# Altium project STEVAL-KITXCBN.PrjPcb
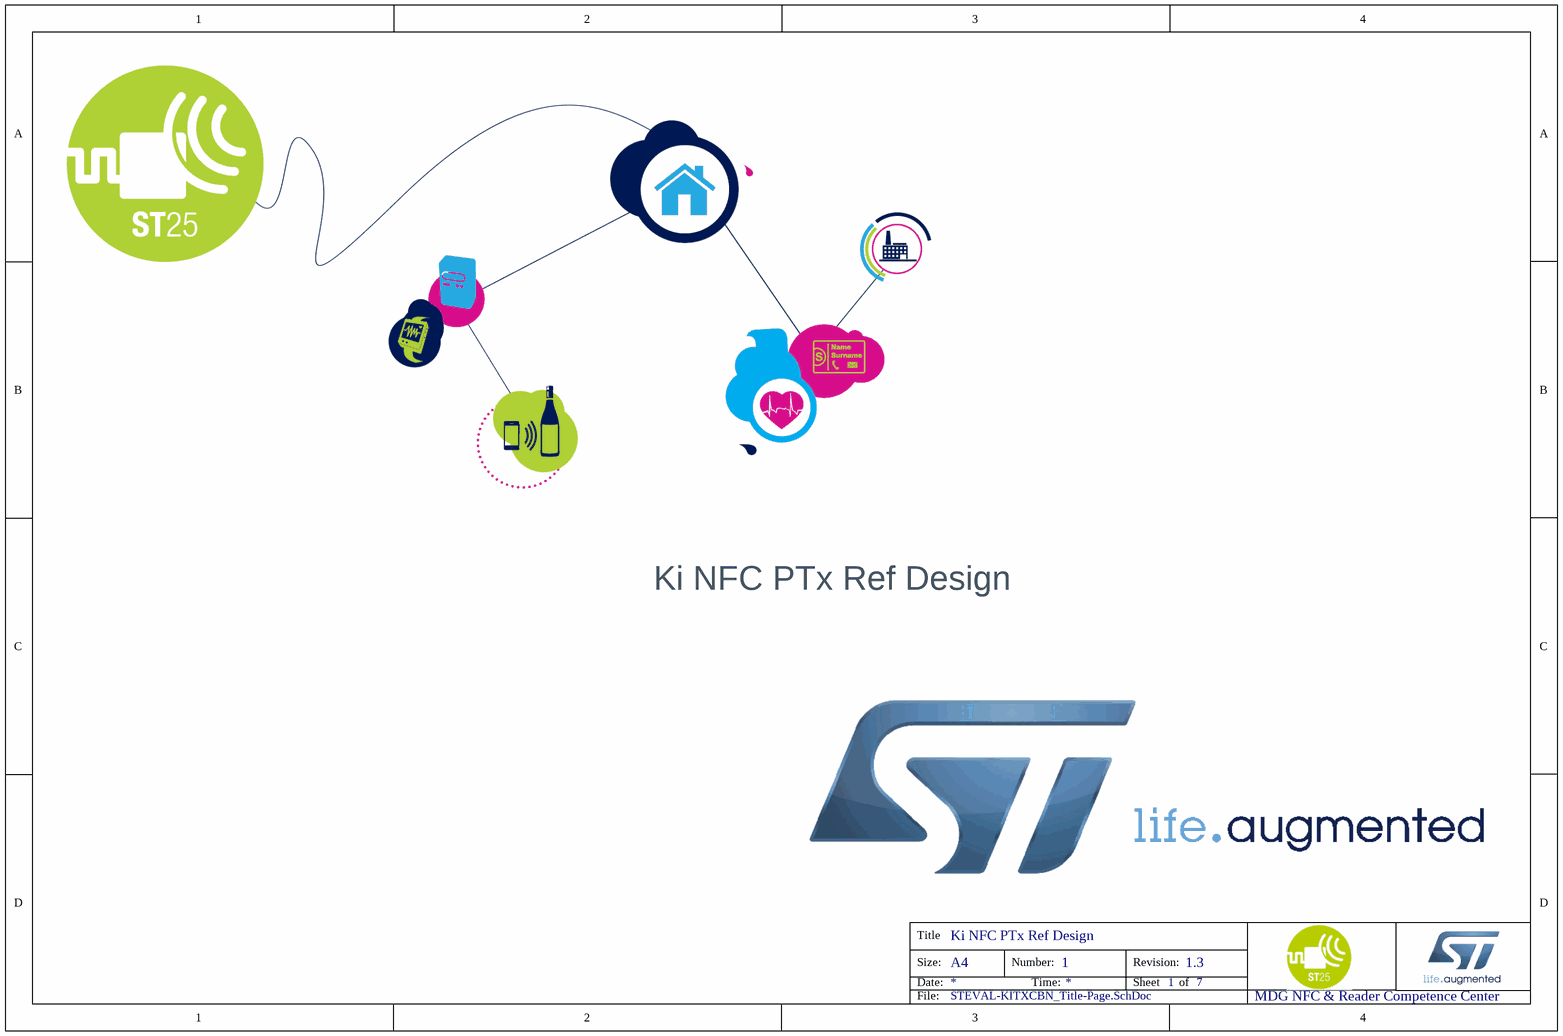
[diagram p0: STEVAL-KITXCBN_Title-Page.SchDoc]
BoardCat: Ki; BoardRef: ST25R3916-Ki; BoardRev: 1.3; Originator: rampetsm; ProjDate: 11.01.2022; ProjTitle: Ki NFC PTx Ref Design; SocProj: None; TotalNrSheets: 7
7 sheets, 229 parts. Net scope: hierarchical (ports join the sheet entries above them; power ports are global).
Board file: STEVAL-KITXCBN.PcbDoc
Sheets:
  STEVAL-KITXCBN_Title-Page.SchDoc
  STEVAL-KITXCBN_Main-Page.SchDoc
  STEVAL-KITXCBN_MCU-Connector.SchDoc
  STEVAL-KITXCBN_Microcontroller.SchDoc
  STEVAL-KITXCBN_NFC.SchDoc
  STEVAL-KITXCBN_Powerstage.SchDoc
  STEVAL-KITXCBN_Power-Supply.SchDoc

## Sheet STEVAL-KITXCBN_Title-Page.SchDoc
size A4; DocumentNumber: 1; SheetNumber: 1; SheetTotal: 7; PageSetup: Record=PageOptions¦CenterHorizontal=True¦CenterVertical=True¦PrintScale=1.00¦XCorrection=1.00¦YCorrection=1.00¦PrintKind=0¦BorderSize=5000000¦LeftOffset=0¦BottomOffset=0¦Orientation=2¦PaperLength=1000¦PaperWidth=1000¦Scale=100¦PaperSource=7¦PrintQuality=-3¦MediaType=1¦DitherType=10¦PrintScaleMode=1¦PaperKind=A4¦PaperIndex=9

## Sheet STEVAL-KITXCBN_Main-Page.SchDoc
size A4; DocumentNumber: 2; SheetNumber: 2; SheetTotal: 7; PageSetup: Record=PageOptions¦CenterHorizontal=True¦CenterVertical=True¦PrintScale=1.00¦XCorrection=1.00¦YCorrection=1.00¦PrintKind=0¦BorderSize=5000000¦LeftOffset=0¦BottomOffset=0¦Orientation=2¦PaperLength=1000¦PaperWidth=1000¦Scale=100¦PaperSource=7¦PrintQuality=-4¦MediaType=1¦DitherType=10¦PrintScaleMode=1¦PaperKind=A4
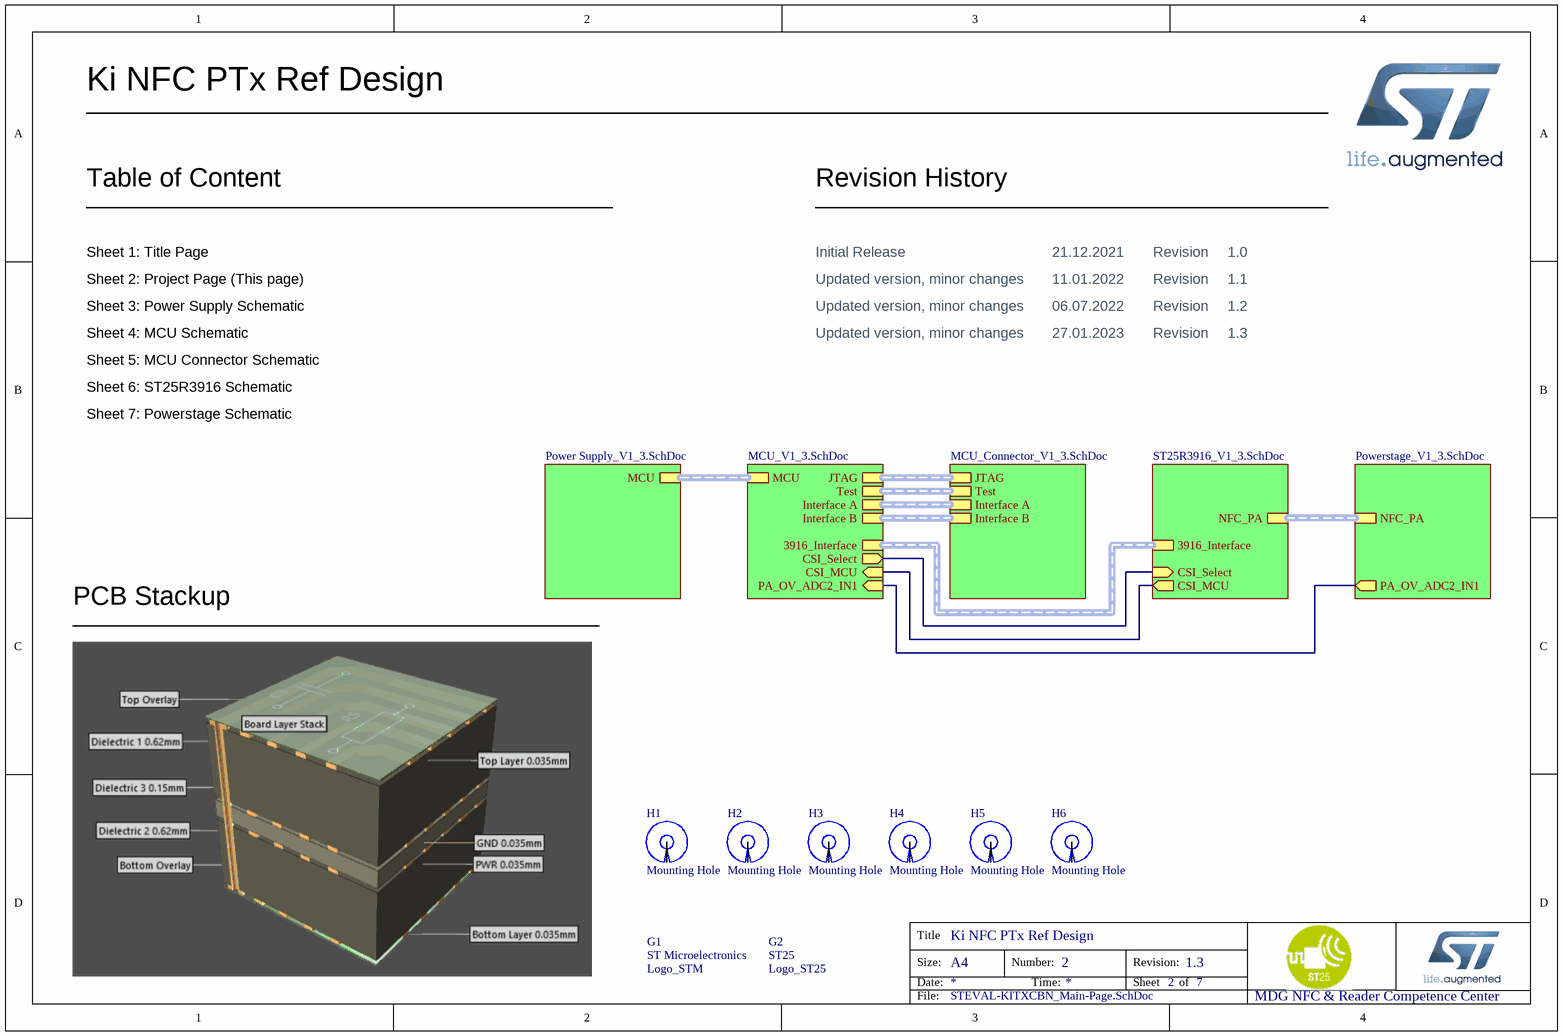
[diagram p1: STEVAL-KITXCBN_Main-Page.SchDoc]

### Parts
G1  Logo_STM  [Logo_STM]
G2  Logo_ST25  [Logo_ST25]
H1  Mounting Hole  [HOLE_M3]  (no BOM)
H2  Mounting Hole  [HOLE_M3]  (no BOM)
H3  Mounting Hole  [HOLE_M3]  (no BOM)
H4  Mounting Hole  [HOLE_M3]  (no BOM)
H5  Mounting Hole  [HOLE_M3]  (no BOM)
H6  Mounting Hole  [HOLE_M3]  (no BOM)

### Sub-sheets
Designator = Power Supply_V1_3.SchDoc (file not in this document): MCU (harness MCU)
Designator = MCU_V1_3.SchDoc (file not in this document): JTAG (harness JTAG), PA_OV_ADC2_IN1 (in), CSI_Select (out), CSI_MCU (in), MCU (harness MCU), 3916_Interface (harness 3916_Interface), Interface A (harness Interface A), Test (harness Test), Interface B (harness Interface B)
Designator = MCU_Connector_V1_3.SchDoc (file not in this document): JTAG (harness JTAG), Interface A (harness Interface A), Interface B (harness Interface B), Test (harness Test)
Designator = ST25R3916_V1_3.SchDoc (file not in this document): CSI_Select (in), CSI_MCU (out), 3916_Interface (harness 3916_Interface), NFC_PA (harness *)
Designator = Powerstage_V1_3.SchDoc (file not in this document): PA_OV_ADC2_IN1 (out), NFC_PA (harness *)

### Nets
(unnamed): sheet Designator/PA_OV_ADC2_IN1, sheet Designator/PA_OV_ADC2_IN1
(unnamed): sheet Designator/CSI_Select, sheet Designator/CSI_Select  [a separate net that carries the same name]
(unnamed): sheet Designator/CSI_MCU, sheet Designator/CSI_MCU  [a separate net that carries the same name]

Not connected (* = marked no-connect by the designer): H1 1; H2 1; H3 1; H4 1; H5 1; H6 1

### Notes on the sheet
- Table of Content
- Revision History
- Sheet 1: Title Page
- Sheet 2: Project Page (This page)
- Sheet 3: Power Supply Schematic
- Initial Release
- Updated version, minor changes
- 21.12.2021
- 06.07.2022
- 11.01.2022
- Revision
- 1.0
- 1.2
- 1.1
- Sheet 4: MCU Schematic
- Sheet 5: MCU Connector Schematic
- 27.01.2023
- 1.3
- Sheet 6: ST25R3916 Schematic
- Sheet 7: Powerstage Schematic
- PCB Stackup

## Sheet STEVAL-KITXCBN_MCU-Connector.SchDoc
size A4; DocumentNumber: 5; SheetNumber: 5; SheetTotal: 7
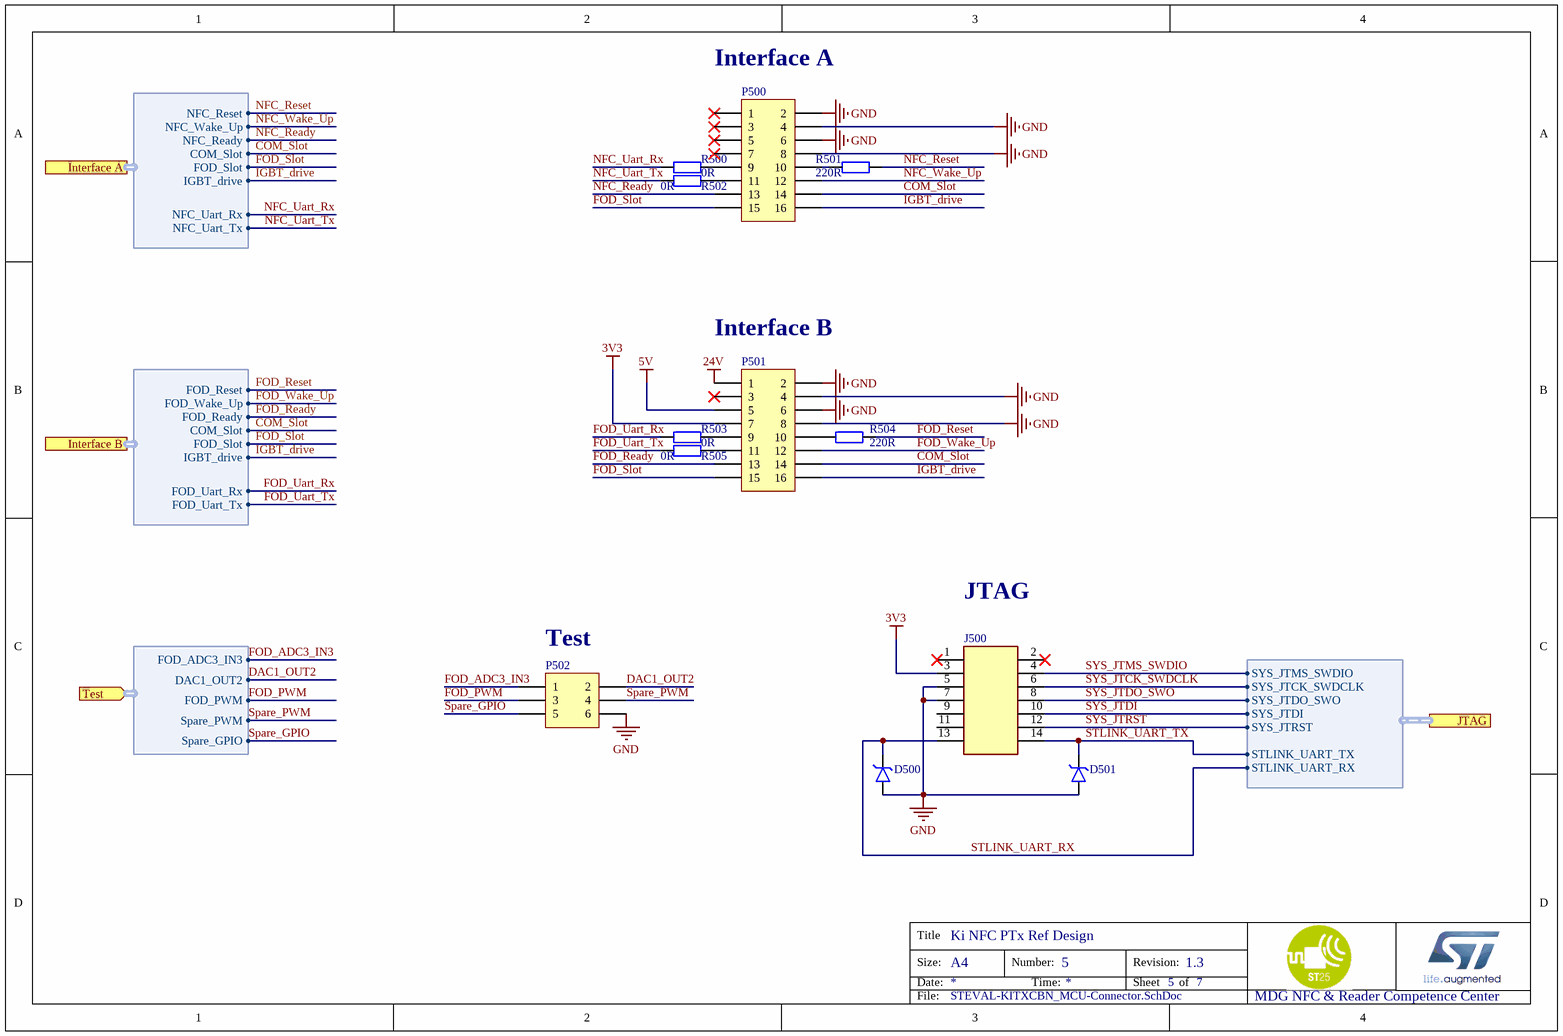
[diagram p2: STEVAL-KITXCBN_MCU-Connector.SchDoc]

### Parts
D500  ESDALC6V1-1U2  [ST-ST0201]  (value not drawn)
D501  ESDALC6V1-1U2  [ST-ST0201]  (value not drawn)
J500  FTSH-107-01-L-DV-K-A  [SAMTEC-FTSH-107-01-X-DV-K-A-WITH-FFSD]  (value not drawn)
P500  Header 8X2_3D_female  [HDR2X8_3D_female]  (value not drawn)
P501  Header 8X2_3D_male  [HDR2X8_3D_male]  (value not drawn)
P502  Header 3X2_3D_male  [HDR2X3_3D_male]  (value not drawn)
R500  0R  [RES_SMD_0805]
R501  220R  [RES_SMD_0805]
R502  0R  [RES_SMD_0805]
R503  0R  [RES_SMD_0805]
R504  220R  [RES_SMD_0805]
R505  0R  [RES_SMD_0805]

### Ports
Interface A (harness Interface A), Interface B (harness Interface B), JTAG (harness JTAG), Test (in, harness Test)

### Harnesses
Interface B: FOD_Slot, IGBT_drive, FOD_Wake_Up, FOD_Reset, COM_Slot, FOD_Uart_Rx, FOD_Uart_Tx, FOD_Ready
Interface A: FOD_Slot, IGBT_drive, NFC_Wake_Up, NFC_Reset, COM_Slot, NFC_Uart_Rx, NFC_Uart_Tx, NFC_Ready
JTAG: SYS_JTMS_SWDIO, SYS_JTCK_SWDCLK, SYS_JTDO_SWO, SYS_JTDI, SYS_JTRST, STLINK_UART_TX, STLINK_UART_RX
Test: FOD_ADC3_IN3, DAC1_OUT2, FOD_PWM, Spare_PWM, Spare_GPIO

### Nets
3V3: J500.3 P501.7
5V: P501.5
24V: P501.1
GND: D500.A D501.A J500.5 J500.7 P500.2 P500.4 P500.6 P500.8 P501.2 P501.4 P501.6 P501.8 P502.6
COM_Slot: P500.14 P501.14 ; port Interface B.COM_Slot, port Interface A.COM_Slot
DAC1_OUT2: P502.2 ; port Test.DAC1_OUT2
FOD_ADC3_IN3: P502.1 ; port Test.FOD_ADC3_IN3
FOD_PWM: P502.3 ; port Test.FOD_PWM
FOD_Ready: P501.13 ; port Interface B.FOD_Ready
FOD_Reset: R504.2 ; port Interface B.FOD_Reset
FOD_Slot: P500.15 P501.15 ; port Interface B.FOD_Slot, port Interface A.FOD_Slot
FOD_Uart_Rx: R503.1 ; port Interface B.FOD_Uart_Rx
FOD_Uart_Tx: R505.1 ; port Interface B.FOD_Uart_Tx
FOD_Wake_Up: P501.12 ; port Interface B.FOD_Wake_Up
IGBT_drive: P500.16 P501.16 ; port Interface B.IGBT_drive, port Interface A.IGBT_drive
NFC_Ready: P500.13 ; port Interface A.NFC_Ready
NFC_Reset: R501.2 ; port Interface A.NFC_Reset
NFC_Uart_Rx: R500.1 ; port Interface A.NFC_Uart_Rx
NFC_Uart_Tx: R502.1 ; port Interface A.NFC_Uart_Tx
NFC_Wake_Up: P500.12 ; port Interface A.NFC_Wake_Up
Spare_GPIO: P502.5 ; port Test.Spare_GPIO
Spare_PWM: P502.4 ; port Test.Spare_PWM
STLINK_UART_RX: D500.K J500.13 ; port JTAG.STLINK_UART_RX
STLINK_UART_TX: D501.K J500.14 ; port JTAG.STLINK_UART_TX
SYS_JTCK_SWDCLK: J500.6 ; port JTAG.SYS_JTCK_SWDCLK
SYS_JTDI: J500.10 ; port JTAG.SYS_JTDI
SYS_JTDO_SWO: J500.8 ; port JTAG.SYS_JTDO_SWO
SYS_JTMS_SWDIO: J500.4 ; port JTAG.SYS_JTMS_SWDIO
SYS_JTRST: J500.12 ; port JTAG.SYS_JTRST
NetP500_9: P500.9 R500.2
NetP500_10: P500.10 R501.1
NetP500_11: P500.11 R502.2
NetP501_9: P501.9 R503.2
NetP501_10: P501.10 R504.1
NetP501_11: P501.11 R505.2

Not connected (* = marked no-connect by the designer): J500 1* 2* 9 11; P500 1* 3* 5* 7*; P501 3*

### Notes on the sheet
- (near P500) Interface A
- (near P501) Interface B
- (near P502) Test
- JTAG

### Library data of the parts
D500 D501 = ESDALC6V1-1U2: ESD PROTECT TRANSIL ESDALC6V1-1U2; Manufacturer: ST MICRO; VERIFIE: YES
J500 = FTSH-107-01-L-DV-K-A: CONNECTOR FTSH-107-01-L-DV-K-A; Manufacturer: SAMTEC; VERIFIE: YES
P500 = Header 8X2_3D_female: Board Connector, 16 Contact(s), 2 Row(s), Female, Straight, 0.1 inch Pitch, Solder Terminal, Black Insulator, Socket; Manufacturer: Würth Electronics; Manufacturer Part Number: 61301621121; Option: General Purpose; Contact Pattern: RECTANGULAR; Contact Style: SQ PIN-SKT; Filter Feature: No; Number Of Connectors: 1; Number Of PCB Rows: 2; Number of Contacts: 16; Contact Resistance: 10mR; Mating Information: MULTIPLE MATING PARTS AVAILABLE; Additional Feature: TIGER BUY CONTACT; Body Breadth: 0.195inch; PCB Contact Row Spacing: 2.54mm; Plating Thickness: 20uin; Body Depth: 0.335inch; Reference Standard: UL; Reliability: COMMERCIAL
P501 = Header 8X2_3D_male: Board Connector, 16 Contact(s), 2 Row(s), Male, Straight, 0.1 inch Pitch, Solder Terminal; Manufacturer: Würth Electronics; Manufacturer Part Number: 61301621121; Manufacturer Series: HTSW; Option: General Purpose; Filter Feature: No; Mating Information: MULTIPLE MATING PARTS AVAILABLE; Number of Rows Loaded: 2; Number of Contacts: 16; Additional Feature: E.L.P.
P502 = Header 3X2_3D_male: Board Connector, 6 Contact(s), 2 Row(s), Male, Straight, 0.1 inch Pitch, Solder Terminal, Black Insulator; Manufacturer: Samtec; Manufacturer Part Number: TSW-103-07-F-D; Option: General Purpose; Additional Feature: E.L.P.; Filter Feature: No; Number of Rows Loaded: 2; Number of Contacts: 6; Mating Information: MULTIPLE MATING PARTS AVAILABLE; Contact Pattern: RECTANGULAR; Contact Style: SQ PIN-SKT; Number Of Connectors: 1; PCB Contact Row Spacing: 5.08mm; Reference Standard: UL; Reliability: COMMERCIAL
R500 R502 R503 R505 = RESISTOR: Metal Glaze/thick Film, 0.0625W, 0ohm, Surface Mount, 0402; Manufacturer: Yageo; Manufacturer Part Number: RC0402JR-070RL; TSL: Yes; Tolerance: 1%; Rated Power Dissipation (P): 62.5mW; Rated Temperature: 70°C; Package Height: 0.35mm; Package Length: 1mm; Package Width: 0.5mm
R501 R504 = RESISTOR: TSL: Yes; Tolerance: 1%

## Sheet STEVAL-KITXCBN_Microcontroller.SchDoc
size A4; DocumentNumber: 4; SheetNumber: 4; SheetTotal: 7
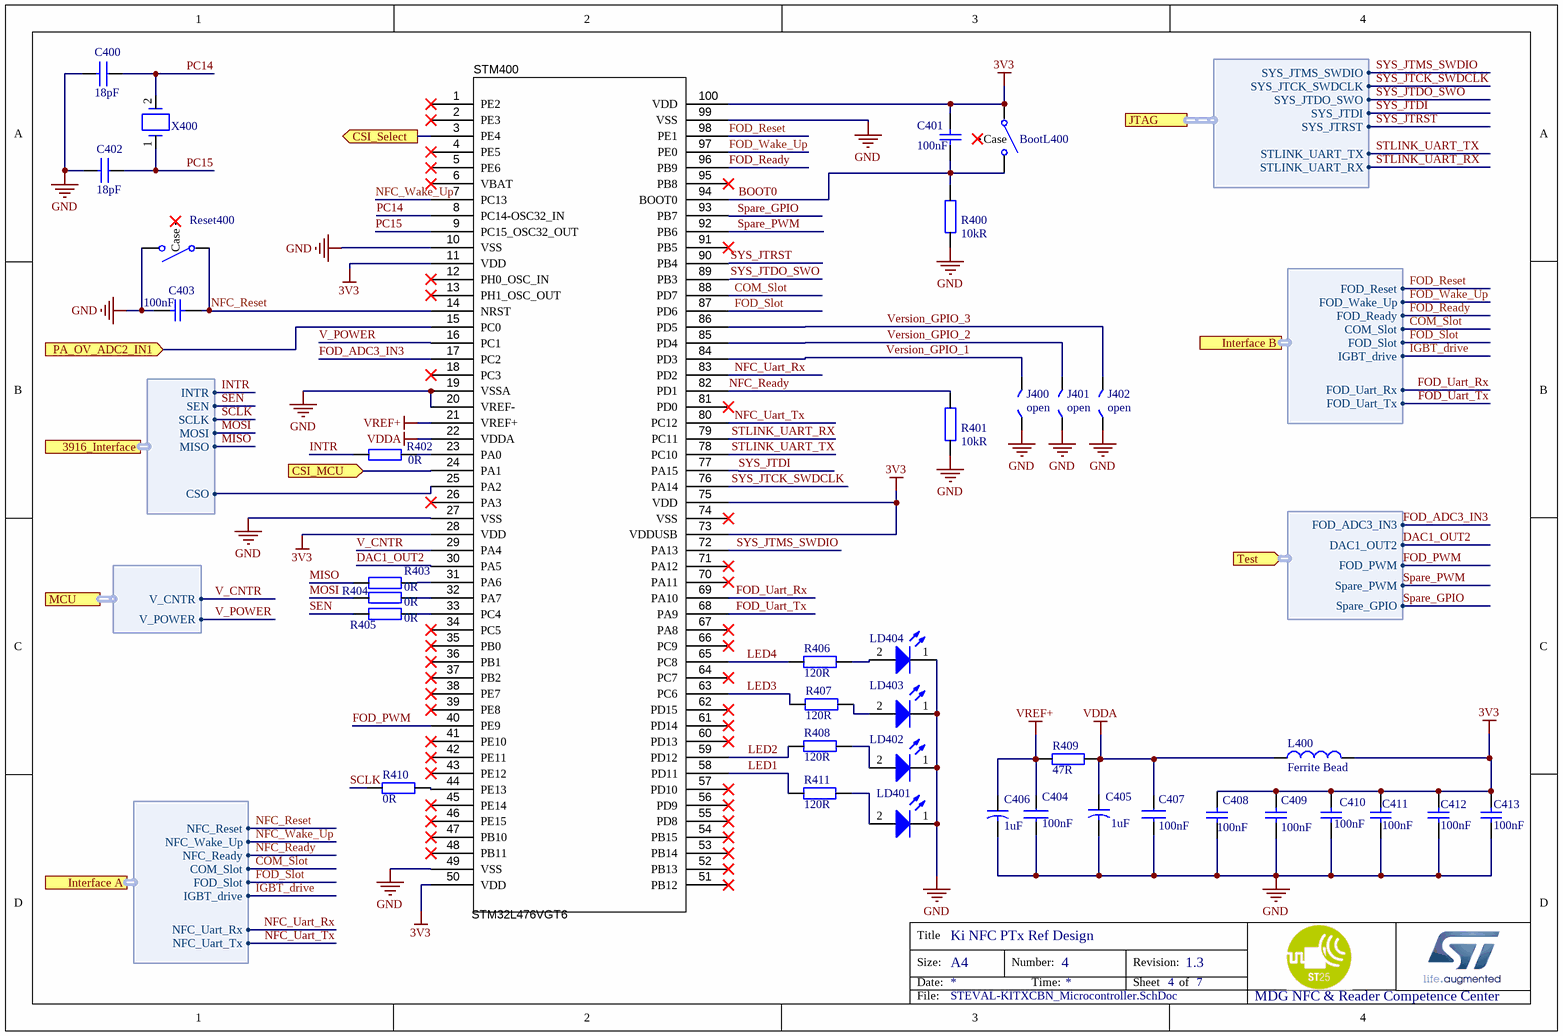
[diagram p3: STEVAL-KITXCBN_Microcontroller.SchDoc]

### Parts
BootL400  PushButton  [SW_SPST_KMR211G]  (value not drawn)
C400  18pF  [C0402]
C401  100nF  [C0402-ss]
C402  18pF  [C0402]
C403  100nF  [C0402-ss]
C404  100nF  [C0402]
C405  1uF  [CP_SMD_A]
C406  1uF  [CP_SMD_A]
C407  100nF  [C0402]
C408  100nF  [C0402-ss]
C409  100nF  [C0402-ss]
C410  100nF  [C0402-ss]
C411  100nF  [C0402-ss]
C412  100nF  [C0402-ss]
C413  100nF  [C0402-ss]
J400  open  [JP2_SMD_open]  (no BOM)
J401  open  [JP2_SMD_open]  (no BOM)
J402  open  [JP2_SMD_open]  (no BOM)
L400  Ferrite Bead  [0603-CAP]
LD401  White LED  [0603D]  (value not drawn)
LD402  White LED  [0603D]  (value not drawn)
LD403  White LED  [0603D]  (value not drawn)
LD404  White LED  [0603D]  (value not drawn)
R400  10kR  [R0402]
R401  10kR  [R0402]
R402  0R  [R0402]
R403  0R  [R0402]
R404  0R  [R0402]
R405  0R  [R0402]
R406  120R  [R0402]
R407  120R  [R0402]
R408  120R  [R0402]
R409  47R  [R0402]
R410  0R  [R0402]
R411  120R  [R0402]
Reset400  PushButton  [SW_SPST_KMR211G]  (value not drawn)
STM400  STM32L476VGT6  [STM32L476VGT6 LQFP100]
X400  32_768kHz  [32_768kHz_Crystal]  (value not drawn)

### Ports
3916_Interface (harness 3916_Interface), CSI_MCU (in), CSI_Select (out), Interface A (harness Interface A), Interface B (harness Interface B), JTAG (harness JTAG), MCU (harness MCU), PA_OV_ADC2_IN1 (in), Test (in, harness Test)

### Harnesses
MCU: V_POWER, V_CNTR
3916_Interface: SEN, INTR, MISO, MOSI, SCLK, CSO
JTAG: SYS_JTMS_SWDIO, SYS_JTCK_SWDCLK, SYS_JTDO_SWO, SYS_JTDI, SYS_JTRST, STLINK_UART_TX, STLINK_UART_RX
Test: FOD_ADC3_IN3, DAC1_OUT2, FOD_PWM, Spare_PWM, Spare_GPIO
Interface A: FOD_Slot, IGBT_drive, NFC_Wake_Up, NFC_Reset, COM_Slot, NFC_Uart_Rx, NFC_Uart_Tx, NFC_Ready
Interface B: FOD_Slot, IGBT_drive, FOD_Wake_Up, FOD_Reset, COM_Slot, FOD_Uart_Rx, FOD_Uart_Tx, FOD_Ready

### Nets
3V3: BootL400.2 C401.1 C408.2 C409.2 C410.2 C411.2 C412.2 C413.2 L400.2 STM400.11(VDD) STM400.28(VDD) STM400.50(VDD) STM400.73(VDDUSB) STM400.75(VDD) STM400.100(VDD)
GND: C400.2 C402.2 C403.1 C404.2 C405.2 C406.2 C407.2 C408.1 C409.1 C410.1 C411.1 C412.1 C413.1 J400.1 J401.1 J402.1 LD401.1(K) LD402.1(K) LD403.1(K) LD404.1(K) R400.1 R401.1 Reset400.1 STM400.10(VSS) STM400.19(VSSA) STM400.20(VREF-) STM400.27(VSS) STM400.49(VSS) STM400.99(VSS)
VDDA: C405.1 C407.1 L400.1 R409.1 STM400.22(VDDA)
VREF+: C404.1 C406.1 R409.2 STM400.21(VREF+)
BOOT0: BootL400.1 C401.2 R400.2 STM400.94(BOOT0)
COM_Slot: STM400.88(PD7) ; port Interface A.COM_Slot, port Interface B.COM_Slot
DAC1_OUT2: STM400.30(PA5) ; port Test.DAC1_OUT2
FOD_ADC3_IN3: STM400.17(PC2) ; port Test.FOD_ADC3_IN3
FOD_PWM: STM400.40(PE9) ; port Test.FOD_PWM
FOD_Ready: STM400.96(PB9) ; port Interface B.FOD_Ready
FOD_Reset: STM400.98(PE1) ; port Interface B.FOD_Reset
FOD_Slot: STM400.87(PD6) ; port Interface A.FOD_Slot, port Interface B.FOD_Slot
FOD_Uart_Rx: STM400.69(PA10) ; port Interface B.FOD_Uart_Rx
FOD_Uart_Tx: STM400.68(PA9) ; port Interface B.FOD_Uart_Tx
FOD_Wake_Up: STM400.97(PE0) ; port Interface B.FOD_Wake_Up
IGBT_drive: port Interface A.IGBT_drive, port Interface B.IGBT_drive
INTR: R402.1 ; port 3916_Interface.INTR
LED1: R411.1 STM400.58(PD11)
LED2: R408.1 STM400.59(PD12)
LED3: R407.1 STM400.63(PC6)
LED4: R406.1 STM400.65(PC8)
MISO: R403.1 ; port 3916_Interface.MISO
MOSI: R404.1 ; port 3916_Interface.MOSI
NFC_Ready: R401.2 STM400.82(PD1) ; port Interface A.NFC_Ready
NFC_Reset: C403.2 Reset400.2 STM400.14(NRST) ; port Interface A.NFC_Reset
NFC_Uart_Rx: STM400.83(PD2) ; port Interface A.NFC_Uart_Rx
NFC_Uart_Tx: STM400.80(PC12) ; port Interface A.NFC_Uart_Tx
NFC_Wake_Up: STM400.7(PC13) ; port Interface A.NFC_Wake_Up
PC14: C400.1 STM400.8(PC14-OSC32_IN) X400.2
PC15: C402.1 STM400.9(PC15_OSC32_OUT) X400.1
SCLK: R410.1 ; port 3916_Interface.SCLK
SEN: R405.1 ; port 3916_Interface.SEN
Spare_GPIO: STM400.93(PB7) ; port Test.Spare_GPIO
Spare_PWM: STM400.92(PB6) ; port Test.Spare_PWM
STLINK_UART_RX: STM400.79(PC11) ; port JTAG.STLINK_UART_RX
STLINK_UART_TX: STM400.78(PC10) ; port JTAG.STLINK_UART_TX
SYS_JTCK_SWDCLK: STM400.76(PA14) ; port JTAG.SYS_JTCK_SWDCLK
SYS_JTDI: STM400.77(PA15) ; port JTAG.SYS_JTDI
SYS_JTDO_SWO: STM400.89(PB3) ; port JTAG.SYS_JTDO_SWO
SYS_JTMS_SWDIO: STM400.72(PA13) ; port JTAG.SYS_JTMS_SWDIO
SYS_JTRST: STM400.90(PB4) ; port JTAG.SYS_JTRST
V_CNTR: STM400.29(PA4) ; port MCU.V_CNTR
V_POWER: STM400.16(PC1) ; port MCU.V_POWER
Version_GPIO_1: J400.2 STM400.84(PD3)
Version_GPIO_2: J401.2 STM400.85(PD4)
Version_GPIO_3: J402.2 STM400.86(PD5)
NetLD401_2: LD401.2(A) R411.2
NetLD402_2: LD402.2(A) R408.2
NetLD403_2: LD403.2(A) R407.2
NetLD404_2: LD404.2(A) R406.2
NetR402_2: R402.2 STM400.23(PA0)
NetR403_2: R403.2 STM400.31(PA6)
NetR404_2: R404.2 STM400.32(PA7)
NetR405_2: R405.2 STM400.33(PC4)
NetR410_2: R410.2 STM400.44(PE13)
NetSTM400_3: STM400.3(PE4) ; port CSI_Select
NetSTM400_15: STM400.15(PC0) ; port PA_OV_ADC2_IN1
NetSTM400_24: STM400.24(PA1) ; port CSI_MCU
NetSTM400_25: STM400.25(PA2) ; port 3916_Interface.CSO

Not connected (* = marked no-connect by the designer): BootL400 0(Case)*; Reset400 0(Case)*; STM400 1(PE2)* 2(PE3)* 4(PE5)* 5(PE6)* 6(VBAT)* 12(PH0_OSC_IN)* 13(PH1_OSC_OUT)* 18(PC3)* 26(PA3)* 34(PC5)* 35(PB0)* 36(PB1)* 37(PB2)* 38(PE7)* 39(PE8)* 41(PE10)* 42(PE11)* 43(PE12)* 45(PE14)* 46(PE15)* 47(PB10)* 48(PB11)* 51(PB12)* 52(PB13)* 53(PB14)* 54(PB15)* 55(PD8)* 56(PD9)* 57(PD10)* 60(PD13)* 61(PD14)* 62(PD15)* 64(PC7)* 66(PC9)* 67(PA8)* 70(PA11)* 71(PA12)* 74(VSS)* 81(PD0)* 91(PB5)* 95(PB8)*

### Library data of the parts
BootL400 Reset400 = SW_SPST2_GND: SWITCH TACTILE SPST-NO 0.05A 32V; Manufacturer: ITT C&K; Manufacturer Part Number: KMR211GLFS; Mechanical Life: 200000Cycles; Power Rating: 1W; Contact Current Rating: 50mA; Operating Force: 1.2N; Throw Configuration: SPST; Illumination Type: Non-Illuminated,Illuminated; Switch Travel: 0.2mm; Switch Function: Off-Mom; Actuator Type: Standard; Actuator Length: 0.5mm
C400 C402 = C_0402: CAPACITOR CERAMIC 18PF 50V, C0G, 5%, 040; Manufacturer: Kyocera AVX; Manufacturer Part Number: 04025A180JAT2A; Temperature Coefficient: 0ppm/°C; Insulation Resistance: 100GR
C401 C403 = C_0603: Capacitor 100 nF 10 VDC 0402 ¦ KEMET C0402C104K8PACTU (Capacitor 100 nF 10 VDC 0402 Ceramic Capacitors).; Tolerance: 10%; Voltage Rating: 10V; Dielectric: X5R; Dissipation Factor: 5%
C404 C407 = C_0402: Manufacturer: Murata; Manufacturer Part Number: GRM155R61H104KE19D; Capacitance: 100; Tolerance: 10; Voltage Rating: 50; Type (Capacitors): X5R
C405 C406 = C_POL_A: Manufacturer: Kyocera / AVX; Manufacturer Part Number: TAJA105K016RNJ; Capacitance: 1; Tolerance: 10; ESR: 11; Voltage Rating: 16
C408-C413 = C_0603: Manufacturer: MURATA; Manufacturer Part Number: GRM155R61H104KE19D; Produktpalette: Baureihe GRM; Kapazität: 0.1; Kapazitätstoleranz: ± 10%; Dielektrikum: X5; Nennspannung: 50; Keramikkondensatorgehäuse: 0402 [Metrisch 1005]; Betriebstemperatur, min.: -55; Betriebstemperatur, max.: 85; Verpackung: Gurtabschnitt; SVHC: No SVHC (15-Jun-2015); Kondensatoranschlüsse: SMD<!--FANDB--><div class="features-and-benefits-container"><div class="features-and-benefits-description"><span class="features-benefits-value">The Murata GRM series capacitors are Multilayer Ceramic Chip Capacitors (MLCC) used for general purpose applications. These MLCC capacitors are classified into temperature compensating and high dielectric constant types depending on the change in electrostatic capacitance due to change in temperature. The temperature compensating capacitors feature a small rate of change in electrostatic capacitance as the temperature changes and are used for applications such as filters and high frequency circuit matching. The high dielectric constant capacitors use materials with a high dielectric constant and feature a large electrostatic capacitance. Typical applications are power supply decoupling and smoothing circuits.</span></div><div class="features-and-benefits-list"><ul class="features-and-benefits-list-list"><li class="features-and-benefits-list-item">Large capacity and small size in a multilayer structure</li><li class="features-and-benefits-list-item">Capacitance value ranging from 0.1pF to 220?F</li><li class="features-and-benefits-list-item">Tin plated external electrodes, excellent solderability</li><li class="features-and-benefits-list-item">Provides good high frequency characteristics</li><li class="features-and-benefits-list-item">Excellent pulse response</li><li class="features-and-benefits-list-item">High reliability</li><li class="features-and-benefits-list-item">Capacitor size varies from 0.4×0.2mm to 5.7×5.0mm</li><li class="features-and-benefits-list-item">Rated voltage of 2.5VDC to 3.15
J400-J402 = solder_jumper_open
L400 = BLM18AG601SN1D: Ferrite Chip, 1 Function(s), 0.5A, 2 Pin(s); Manufacturer: MURATA; VERIFIE: YES; DC Resistance-Max: 380mR; Max Frequency: 100MHz; Number of Functions: 1; Output Impedance: 600R; Current Rating: 500mA
LD401-LD404 = LED2: LED Uni-Color White 7000K 2-Pin Chip 0603(1608Metric) T/R / LED COOL WHITE 0603 SMD; Manufacturer: Vishay Semiconductors; Manufacturer Part Number: VLMW1300-GS08; Luminous Intensity: 180mcd; Forward Voltage: 3.15V; Viewing Angle: 130°; Lens Style: Square,Rectangular,Clear; Forward Current: 5mA; Power Rating: 70mW; Number of LEDs: 1
R400 R401 = R_0402: Fixed Resistor, Metal Glaze/thick Film, 0.1W, 10000ohm, 50V, 1% +/-Tol, 200ppm/Cel, Surface Mount, 0402; Manufacturer: Panasonic; Manufacturer Part Number: ERJ-U02F1002X; Rated Power Dissipation (P): 100mW; Rated Temperature: 70°C; Temperature Coefficient: 200ppm/°C; Package Height: 0.35mm; Package Length: 1mm; Package Width: 0.5mm; Reference Standard: AEC-Q200
R402-R405 R410 = R_0402: Metal Glaze/thick Film, 0.0625W, 0ohm, Surface Mount, 0402; Manufacturer: Yageo; Manufacturer Part Number: RC0402JR-070RL; Rated Power Dissipation (P): 62.5mW; Rated Temperature: 70°C; Package Height: 0.35mm; Package Length: 1mm; Package Width: 0.5mm
R406-R408 R411 = R_0402: VISHAY - CRCW0402120RFKED - RES, THICK FILM, 120R, 1%, 0.063W, 0402, REEL; Temperature Coefficient: 100ppm/°C; Power Rating: 63mW; Voltage Rating: 50V
R409 = R_0402: VISHAY - CRCW040247R0FKED - SMD Chip Resistor, 0402 [1005 Metric], 47 ohm, CRCW e3 Series, 50 V, Thick Film, 63 mW; Tolerance: 1%; Temperature Coefficient: 100ppm/°C; Voltage Rating: 50V; Power Rating: 63mW
STM400 = STM32L476VGT6: RISC Microcontroller, 32-Bit, FLASH, CORTEX-M4 CPU, 80MHz, CMOS, PQFP100; Manufacturer: STMicroelectronics
X400 = 32_768kHz_Crystal: FOX ELECTRONICS         FX135A-327            CRYSTAL, 32.768KHZ, 9PF, 3.2 X 1.5MM; Frequency Tolerance: 20ppm; Load Capacitance: 12.5pF; Series Resistance: 70kR; Frequency Stability: -0.045ppm; Operating Frequency: 32.768 MHz

## Sheet STEVAL-KITXCBN_NFC.SchDoc
size A4; DocumentNumber: 6; SheetNumber: 5; SheetTotal: 7
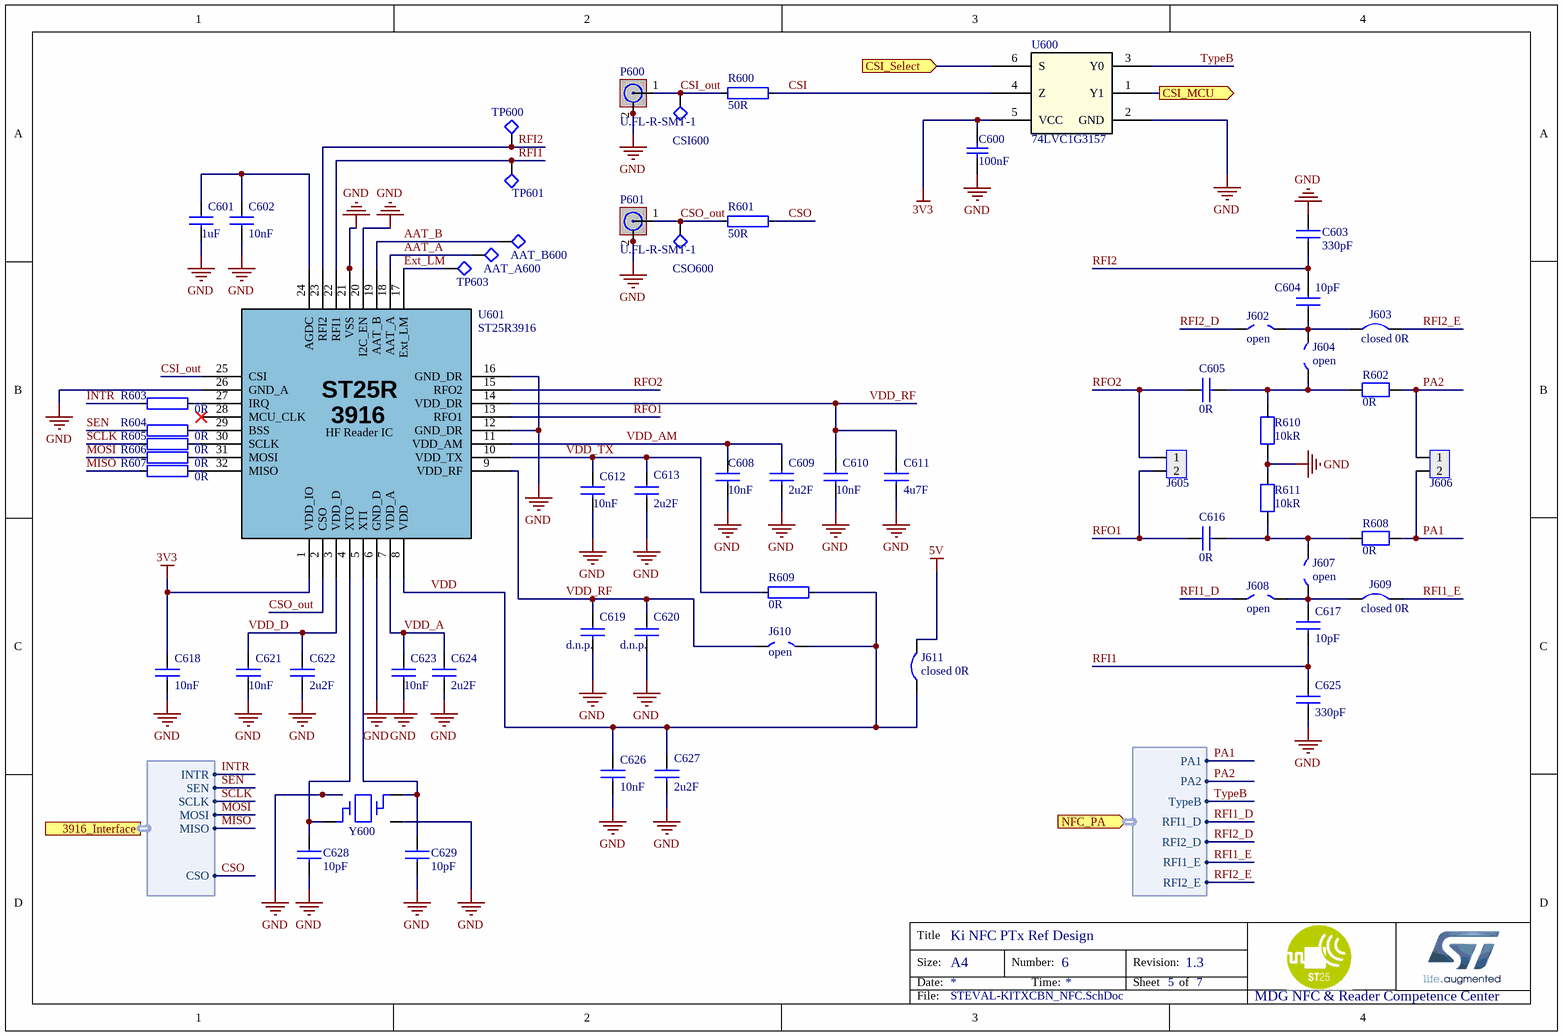
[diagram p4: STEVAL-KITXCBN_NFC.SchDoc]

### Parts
AAT_A600  *  [TP_0.5]  (value not drawn)  (no BOM)
AAT_B600  *  [TP_0.5]  (value not drawn)  (no BOM)
C600  100nF  [C0402-ss]
C601  1uF  [C0402]
C602  10nF  [C0402]
C603  330pF  [C0603]
C604  10pF  [C0603]
C605  0R  [C0603]
C608  10nF  [C0402]
C609  2u2F  [C0402]
C610  10nF  [C0402]
C611  4u7F  [C0402]
C612  10nF  [C0402]
C613  2u2F  [C0402]
C616  0R  [C0603]
C617  10pF  [C0603]
C618  10nF  [C0402]
C619  d.n.p.  [C0402]
C620  d.n.p.  [C0402]
C621  10nF  [C0402]
C622  2u2F  [C0402]
C623  10nF  [C0402]
C624  2u2F  [C0402]
C625  330pF  [C0603]
C626  10nF  [C0402]
C627  2u2F  [C0402]
C628  10pF  [C0402]
C629  10pF  [C0402]
CSI600  *  [TP_0.5]  (value not drawn)  (no BOM)
CSO600  *  [TP_0.5]  (value not drawn)  (no BOM)
J602  open  [JP2_SMD_open_0402]  (net tie, no BOM)
J603  closed 0R  [JP2_SMD_closed]  (net tie)
J604  open  [JP2_SMD_open_0402]  (net tie, no BOM)
J605  d.n.p.  [HDR1X2_slim]  (value not drawn)  (no BOM)
J606  d.n.p.  [HDR1X2_slim]  (value not drawn)  (no BOM)
J607  open  [JP2_SMD_open_0402]  (net tie, no BOM)
J608  open  [JP2_SMD_open_0402]  (net tie, no BOM)
J609  closed 0R  [JP2_SMD_closed]  (net tie)
J610  open  [JP2_SMD_open_0402]  (net tie, no BOM)
J611  closed 0R  [JP2_SMD_closed]  (net tie)
P600  U.FL-R-SMT-1  [U FL Socket - HRS - Surface Mount]
P601  U.FL-R-SMT-1  [U FL Socket - HRS - Surface Mount]
R600  50R  [R0402]
R601  50R  [R0402]
R602  0R  [R0603]
R603  0R  [R0402]
R604  0R  [R0402]
R605  0R  [R0402]
R606  0R  [R0402]
R607  0R  [R0402]
R608  0R  [R0603]
R609  0R  [R0402]
R610  10kR  [R0805]
R611  10kR  [R0805]
TP600  *  [TP_0.5]  (value not drawn)  (no BOM)
TP601  *  [TP_0.5]  (value not drawn)  (no BOM)
TP603  *  [TP_0.5]  (value not drawn)  (no BOM)
U600  74LVC1G3157  [XSON6_SOT1202]
U601  ST25R3916  [ST25R3916-QFN32_5X5_0.5]
Y600  NDK 27,12MHz Crystal  [XRCGB_F_MN]  (value not drawn)

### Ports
3916_Interface (harness 3916_Interface), CSI_MCU (out), CSI_Select (in), NFC_PA (in, harness *)

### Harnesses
3916_Interface: SEN, INTR, MISO, MOSI, SCLK, CSO
*: PA1, PA2, TypeB, RFI1_D, RFI2_D, RFI1_E, RFI2_E

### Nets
3V3: C600.2 C618.1 U600.5(VCC) U601.1(VDD_IO)
5V: J611.2
GND: C600.1 C601.2 C602.2 C603.1 C608.2 C609.2 C610.2 C611.2 C612.2 C613.2 C618.2 C619.2 C620.2 C621.2 C622.2 C623.2 C624.2 C625.2 C626.2 C627.2 C628.2 C629.2 P600.2 P600.3 P601.2 P601.3 R610.2 R611.1 U600.2(GND) U601.6(GND_D) U601.12(GND_DR) U601.16(GND_DR) U601.20(I2C_EN) U601.21(VSS) U601.26(GND_A) U601.33(VSS) Y600.2 Y600.4
AAT_A: AAT_A600.1 U601.18(AAT_A)
AAT_B: AAT_B600.1 U601.19(AAT_B)
CSI: R600.1 U600.4(Z)
CSI_out: CSI600.1 P600.1 R600.2 U601.25(CSI)
CSO: R601.1 ; port 3916_Interface.CSO
CSO_out: CSO600.1 P601.1 R601.2 U601.2(CSO)
Ext_LM: TP603.1 U601.17(Ext_LM)
INTR: R603.2 ; port 3916_Interface.INTR
MISO: R607.2 ; port 3916_Interface.MISO
MOSI: R606.2 ; port 3916_Interface.MOSI
PA1: J606.2 R608.2 ; port NFC_PA.PA1
PA2: J606.1 R602.2 ; port NFC_PA.PA2
RFI1: C617.2 C625.1 TP601.1 U601.22(RFI1)
RFI1_D: J608.1 ; port NFC_PA.RFI1_D
RFI1_E: J609.2 ; port NFC_PA.RFI1_E
RFI2: C603.2 C604.1 TP600.1 U601.23(RFI2)
RFI2_D: J602.1 ; port NFC_PA.RFI2_D
RFI2_E: J603.2 ; port NFC_PA.RFI2_E
RFO1: C616.1 J605.2 U601.13(RFO1)
RFO2: C605.1 J605.1 U601.15(RFO2)
SCLK: R605.2 ; port 3916_Interface.SCLK
SEN: R604.2 ; port 3916_Interface.SEN
TypeB: U600.3(Y0) ; port NFC_PA.TypeB
VDD: C626.1 C627.1 J610.2 J611.1 R609.1 U601.8(VDD)
VDD_A: C623.1 C624.1 U601.7(VDD_A)
VDD_AM: C608.1 C609.1 U601.11(VDD_AM)
VDD_D: C621.1 C622.1 U601.3(VDD_D)
VDD_RF: C610.1 C611.1 C619.1 C620.1 J610.1 U601.9(VDD_RF) U601.14(VDD_DR)
VDD_TX: C612.1 C613.1 R609.2 U601.10(VDD_TX)
NetC601_1: C601.1 C602.1 U601.24(AGDC)
NetC604_2: C604.2 J602.2 J603.1 J604.2
NetC605_2: C605.2 J604.1 R602.1 R610.1
NetC616_2: C616.2 J607.2 R608.1 R611.2
NetC617_1: C617.1 J607.1 J608.2 J609.1
NetC628_1: C628.1 U601.4(XTO) Y600.3
NetC629_1: C629.1 U601.5(XTI) Y600.1
NetR603_1: R603.1 U601.27(IRQ)
NetR604_1: R604.1 U601.29(BSS)
NetR605_1: R605.1 U601.30(SCLK)
NetR606_1: R606.1 U601.31(MOSI)
NetR607_1: R607.1 U601.32(MISO)
NetU600_1: U600.1(Y1) ; port CSI_MCU
NetU600_6: U600.6(S) ; port CSI_Select

Not connected (* = marked no-connect by the designer): U601 28(MCU_CLK)*

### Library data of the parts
AAT_A600 AAT_B600 CSI600 CSO600 TP600 TP601 TP603 = Test point 0.5mm
C600 = C_0603: as C408 on sheet STEVAL-KITXCBN_Microcontroller
C601 = C_1µ_0402_X5R: 1u_X5R; Manufacturer: MURATA; Manufacturer Part Number: GRM155R61C105KA12D; 2nd Source: 0402, 1 µF, 16 V, ± 10%, X5R,
C602 C608 C610 C612 C618 C621 C623 C626 = C_10n_0402_X7R: 10n_x7R; Manufacturer: AVX; Manufacturer Part Number: 04023C103KAT2A; 2nd Source: 0402, 0.01 µF, 25 V, ± 10%, X7R
C603 C625 = C_120p_0603: 120p_COG; Manufacturer: MURATA; Manufacturer Part Number: GRM1885C1H121GA01D; 2nd Source: 120pF ±2% 50V  C0G, NP0 0603
C604 C617 = C_10p_0603: 10p_COG; Manufacturer: MULTICOMP; Manufacturer Part Number: MC0603N100F500CT; 2nd Source: 0603, 10pF, 50 V, 1%, C0G / NP0
C605 C616 = C_68p_0603: Cap Ceramic 0.1uF 50V X7R 10% Pad SMD 0805 FlexiTerm 125C Automotive T/R; Manufacturer: Kyocera AVX; Manufacturer Part Number: 08055C104K4Z2A; Capacitance: 100nF; Temperature Coefficient: 30ppm/°C
C609 C613 C622 C624 C627 = C_2µ2_0402_X5R: 2u2_X5R; Manufacturer: MURATA; Manufacturer Part Number: GRM155R60J225ME15D; 2nd Source: 0402, 2.2 µF, 6.3 V, ± 20%, X5R
C611 = C_4µ7_0402_X5R: 4u7_X5R; Manufacturer: TDK; Manufacturer Part Number: C1005X5R0J475K050BC; 2nd Source: 0402, 4.7 µF, 6.3 V, ± 10%, X5R
C619 C620 = C_2µ2_0402_X5R: Manufacturer: MURATA; Manufacturer Part Number: GRM155R60J225ME15D; 2nd Source: 0402, 2.2 µF, 6.3 V, ± 20%, X5R
C628 C629 = C_10p_0402: 10p_COG; Manufacturer: MURATA; Manufacturer Part Number: GRM1555C1H100GA01D; 2nd Source: 10pF ±2% 50V  C0G, NP0 0402
J602 J604 J607 J608 J610 = solder_jumper_open_0402
J603 J609 J611 = solder_jumper_closed: 0R; Manufacturer: Multicomp; Manufacturer Part Number: MC00625W040210R
J605 J606 = Header 2: Male Single Row Horizontal 2 pin; 2nd Source: doublesourcing allowed
P600 P601 = U.FL-R-SMT-1: Manufacturer: Würth Electronics; Manufacturer Part Number: 636101111001; 2nd Source: yes
R600 R601 = R0402_50R: 50R, 0402; Manufacturer: MULTICOMP; Manufacturer Part Number: MCMR04X49R9FTL; 2nd Source: 49.9 ohm, 50 V, 0402, >62.5 mW, ± 1%
R602 R608 = R_0603: Res Thick Film 0603 0 Ohm Molded SMD Automotive Paper T/R; Manufacturer: Vishay Dale; Manufacturer Part Number: CRCW06030000Z0EAHP; Resistance: 0mR; Power Rating: 250mW; Voltage Rating: 75V; Temperature Coefficient: 0ppm/°C
R603-R607 R609 = R0402_0R: 0R, 0402; Manufacturer: MULTICOMP; Manufacturer Part Number: MC00625W040210R; 2nd Source: 0 ohm, 50 V, 0402, >62.5 mW
R610 R611 = R_0805: Fixed Resistor, Metal Glaze/thick Film, 0.125W, 10000ohm, 150V, 1% +/-Tol, 100ppm/Cel, Surface Mount, 0805; Manufacturer: Yageo; Manufacturer Part Number: RC0805FR-0710KL; Rated Power Dissipation (P): 125mW; Rated Temperature: 70°C; Temperature Coefficient: 100ppm/°C; Additional Feature: LASER TRIMMABLE; Package Height: 0.5mm; Package Length: 2mm; Package Width: 1.25mm
U600 = 74LVC1G3157: 74LVC1G3157 - 2-channel analog multiplexer/demultiplexer; Manufacturer: NXP Semiconductors; Manufacturer Part Number: 74LVC1G3157GS,132; Propagation Delay: 3ns; Max Supply Voltage: 5.5V; Min Supply Voltage: 1.65V; Max Power Dissipation: 250mW; Number of Inputs: 2; Number of Outputs: 1; Logic Function: Multiplexer,Demultiplexer; On-State Resistance: 15R; Operating Supply Current: 40uA; Supply Type: Single; High Level Output Current: 50mA
U601 = ST25R3916: NFC Initiator / HF Reader IC; Manufacturer: STMicroelectronics; Manufacturer Part Number: ST25R3916-AQFMCT-ND
Y600 = NDK NX2016SA: Crystal 27.12MHZ 6PF SMD; Manufacturer Part Number: NX2016SA-27.12MHZ-EXS00A-CS11337

## Sheet STEVAL-KITXCBN_Powerstage.SchDoc
size A4; DocumentNumber: 7; SheetNumber: 6; SheetTotal: 7; SPICEModelCachePSNYJHOY: <root> / <DocumentId>PSNYJHOY</DocumentId> / </root>
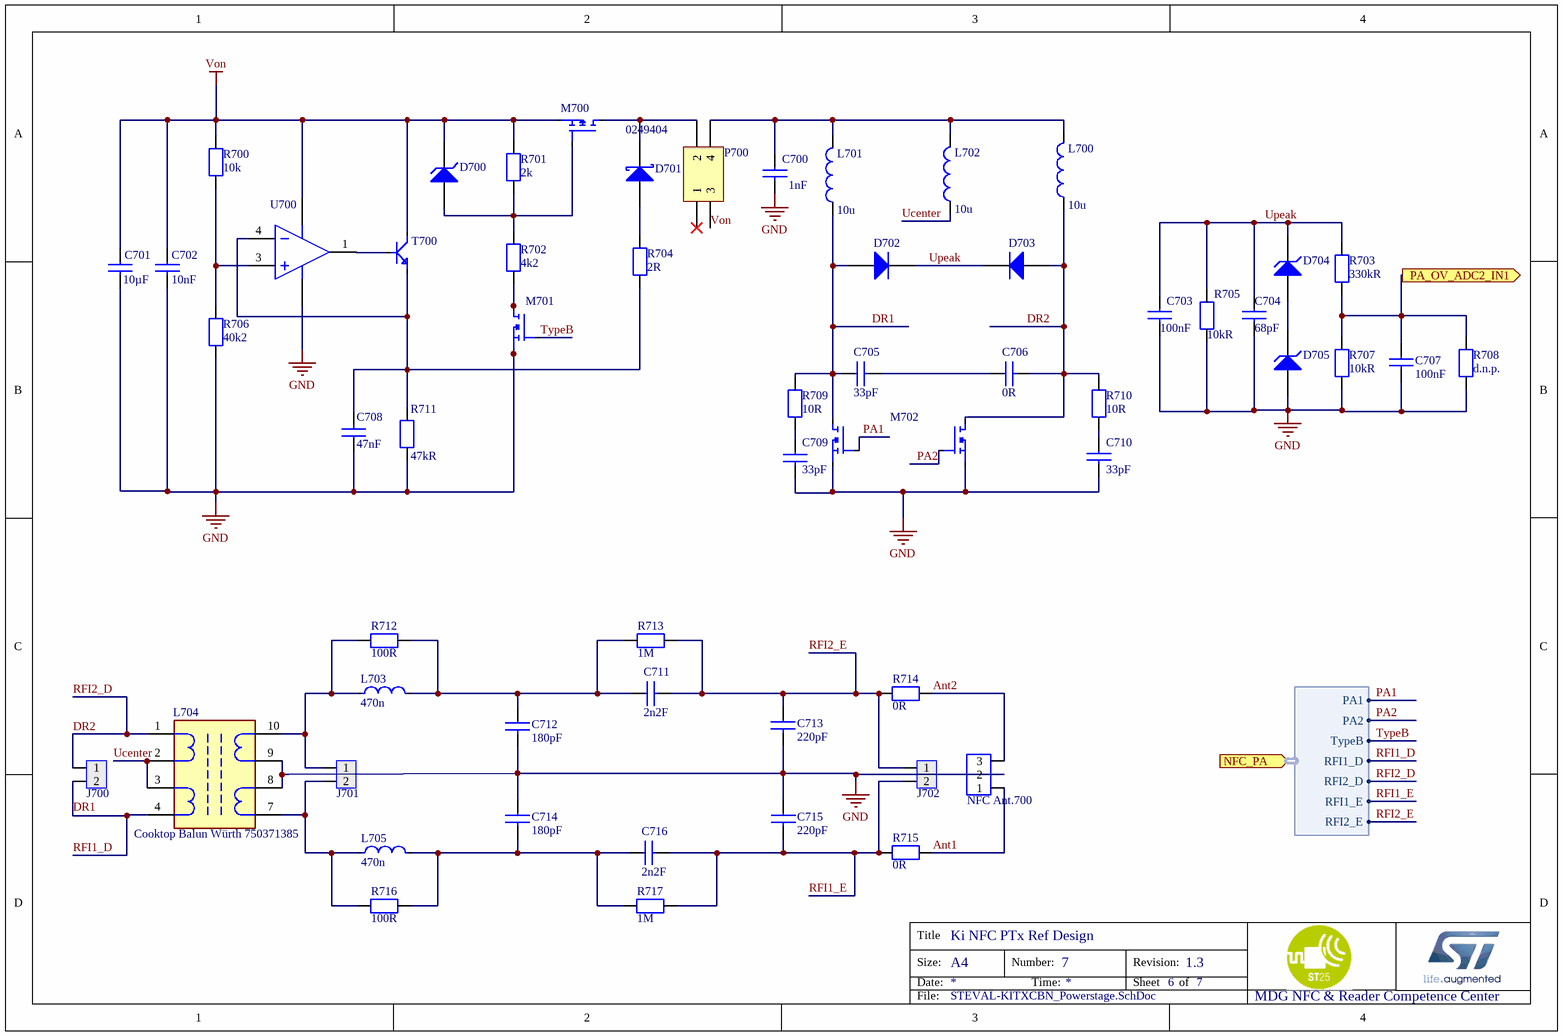
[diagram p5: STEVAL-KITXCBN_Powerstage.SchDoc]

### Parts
C700  1nF  [C0805]
C701  10µF  [C0805]
C702  10nF  [C0805]
C703  100nF  [C0805]
C704  68pF  [C0805]
C705  33pF  [C0603]
C706  0R  [C0603]
C707  100nF  [C0805]
C708  47nF  [C0603]
C709  33pF  [C0805]
C710  33pF  [C0805]
C711  2n2F  [C0603]
C712  180pF  [C0603]
C713  220pF  [C0603]
C714  180pF  [C0603]
C715  220pF  [C0603]
C716  2n2F  [C0603]
D700  (no value)  [ONSC-SOD-123-2-425-04_V]
D701  Supplier Part Number 1: 0249404  [STM-SMB_P_V]  (hidden comment: STPS2L25U)
D702  MMSD4148T1G  [ONSC-SOD-123-2-425-04_V]  (value not drawn)
D703  MMSD4148T1G  [ONSC-SOD-123-2-425-04_V]  (value not drawn)
D704  (no value)  [ONSC-SOD-123-2-425-04_V]
D705  (no value)  [ONSC-SOD-123-2-425-04_V]
J700  d.n.p.  [HDR1X2_slim]  (value not drawn)  (no BOM)
J701  d.n.p.  [HDR1X2_slim]  (value not drawn)  (no BOM)
J702  d.n.p.  [HDR1X2_slim]  (value not drawn)  (no BOM)
L700  value 10u  [WE-PD 1050]  (hidden comment: 7447714100)
L701  value 10u  [WE-PD 1050]  (hidden comment: 7447714100)
L702  value 10u  [WE-PD 1050]  (hidden comment: 7447714100)
L703  470n  [FP-LQM31PN_00-MFG]
L704  Cooktop Balun Würth 750371385  [Wurth Cooktop Balun]
L705  470n  [FP-LQM31PN_00-MFG]
M700  SSM3J353F,LF  [RSR020P05 SOT23-3L]  (value not drawn)
M701  NMOS STT6N3LLH6  [STT6N3LLH6 SOT23-6L]  (value not drawn)
M702  QS6K21FRATR  [NDC7002N TSOT23 6-Lead]  (value not drawn)
NFC_Ant.700  Screw Terminal  [TERMINAL MKDS 1/ 3-3.81]  (value not drawn)
P700  Header 2X2  [HDR2X2]  (value not drawn)
R700  10k  [R0603]
R701  2k  [R0603]
R702  4k2  [R0603]
R703  330kR  [R0805]
R704  2R  [R0603]
R705  10kR  [R0805]
R706  40k2  [R0603]
R707  10kR  [R0805]
R708  d.n.p.  [R0805]
R709  10R  [R0805]
R710  10R  [R0805]
R711  47kR  [R0603]
R712  100R  [R0603]
R713  1M  [R0603]
R714  0R  [R0603]
R715  0R  [R0603]
R716  100R  [R0603]
R717  1M  [R0603]
T700  NPN STD1802T4  [STD1802 DPAK]  (value not drawn)
U700  THS4304DBVTG4  [TI-DBV5_N]  (value not drawn)

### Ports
NFC_PA (in, harness *), PA_OV_ADC2_IN1 (out)

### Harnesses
*: PA1, PA2, TypeB, RFI1_D, RFI2_D, RFI1_E, RFI2_E

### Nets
GND: C700.2 C701.2 C702.2 C703.2 C704.2 C707.2 C708.1 C709.2 C710.2 C712.2 C713.2 C714.1 C715.1 D705.2(A) L704.8(Sec_Cntr) L704.9(Sec_Cntr) M701.4 M702.2 M702.5 NFC_Ant.700.2 R705.2 R706.2 R707.2 R708.2 R711.2 U700.2(VS-)
Von: C701.1 C702.1 D700.1(K) M700.2 P700.3 R700.1 R701.1 T700.2 T700.4 U700.5(VS+)
Ant1: NFC_Ant.700.1 R715.2
Ant2: NFC_Ant.700.3 R714.2
DR1: C705.1 D702.2(A) J700.2 L701.1 L704.4(Prim2) M702.4 R709.1 ; port NFC_PA.RFI1_D  [also labelled RFI1_D]
DR2: C706.2 D703.2(A) J700.1 L700.1 L704.1(Prim1) M702.6 R710.1 ; port NFC_PA.RFI2_D  [also labelled RFI2_D]
PA1: M702.3 ; port NFC_PA.PA1
PA2: M702.1 ; port NFC_PA.PA2
RFI1_E: C715.2 C716.2 J702.2 R715.1 R717.2 ; port NFC_PA.RFI1_E
RFI2_E: C711.2 C713.1 J702.1 R713.2 R714.1 ; port NFC_PA.RFI2_E
TypeB: M701.3 ; port NFC_PA.TypeB
Ucenter: L702.1 L704.2(Prim_Cntr) L704.3(Prim_Cntr)
Upeak: C703.1 C704.1 D702.1(K) D703.1(K) D704.1(K) R703.1 R705.1
NetC700_1: C700.1 L700.2 L701.2 L702.2 P700.4
NetC705_2: C705.2 C706.1
NetC707_1: C707.1 R703.2 R707.1 R708.1 ; port PA_OV_ADC2_IN1
NetC708_2: C708.2 R704.2 R711.1 T700.3 U700.4(IN-)
NetC709_1: C709.1 R709.2
NetC710_1: C710.1 R710.2
NetC711_1: C711.1 C712.1 L703.2 R712.2 R713.1
NetC714_2: C714.2 C716.1 L705.2 R716.2 R717.1
NetD700_2: D700.2(A) M700.1 R701.2 R702.1
NetD701_1: D701.1(A) R704.1
NetD701_2: D701.2(K) M700.3 P700.2
NetD704_2: D704.2(A) D705.1(K)
NetJ701_1: J701.1 L703.1 L704.10(Sec1) R712.1
NetJ701_2: J701.2 L704.7(Sec2) L705.1 R716.1
NetM701_1: M701.1 M701.2 M701.5 M701.6 R702.2
NetR700_2: R700.2 R706.1 U700.3(IN+)
NetT700_1: T700.1 U700.1(VOUT)

Not connected (* = marked no-connect by the designer): P700 1*

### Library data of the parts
C700 = C_0805: Ceramic Capacitor, Multilayer, Ceramic, 100V, 5% +Tol, 5% -Tol, C0G, 30ppm/Cel TC, 0.001uF, Surface Mount, 0805; Manufacturer: Kyocera AVX; Manufacturer Part Number: 08051A102JAT2A; Multilayer: Yes
C701 = C_0805: Ceramic Capacitor, Multilayer, Ceramic, 25V, 10% +Tol, 10% -Tol, X5R, 15% TC, 10uF, Surface Mount, 0805; Manufacturer: Murata; Manufacturer Part Number: GRM21BR61E106KA73L; Multilayer: Yes
C702 = C_0805: Ceramic Capacitor, Ceramic, 50V, 10% +Tol, 10% -Tol, X7R, -/+15ppm/Cel TC, 0.01uF, 0805; Manufacturer: KEMET; Manufacturer Part Number: C0805F103K5RACTU
C703 C707 = C_0805: Ceramic Capacitor, Multilayer, Ceramic, 50V, 10% +Tol, 10% -Tol, X7R, 15% TC, 0.1uF, Surface Mount, 0805; Manufacturer: Kyocera AVX; Manufacturer Part Number: 08055C104K4Z2A; Multilayer: Yes; Reference Standard: AEC-Q200
C704 = C_0805: Ceramic Capacitor, Multilayer, Ceramic, 100V, 5% +Tol, 5% -Tol, C0G, -/+30ppm/Cel TC, 0.000068uF, Surface Mount, 0805; Manufacturer: KEMET; Manufacturer Part Number: C0805C680J1GACTU; Multilayer: Yes
C705 = C_0603: Ceramic Capacitor, Multilayer, Ceramic, 100V, 5% +Tol, 5% -Tol, C0G, 30ppm/Cel TC, 0.000015uF, Surface Mount, 0603; Manufacturer: KEMET; Manufacturer Part Number: C0603C150J1GACTU; Value: 15pF; Multilayer: Yes
C706 = C_0603: Ceramic Capacitor, Multilayer, Ceramic, 100V, 5% +Tol, 5% -Tol, C0G, 30ppm/Cel TC, 0.000022uF, Surface Mount, 0603; Manufacturer: KEMET; Manufacturer Part Number: C0603C220J1GACTU; Value: 22pF; Multilayer: Yes
C708 = C_0603: Ceramic Capacitor, Multilayer, Ceramic, 100V, 10% +Tol, 10% -Tol, X7R, 15% TC, 0.047uF, Surface Mount, 0603; Manufacturer: KEMET; Manufacturer Part Number: C0603C473K1RACTU; Multilayer: Yes
C709 C710 = C_0805: Ceramic Capacitor, Multilayer, Ceramic, 100V, 5% +Tol, 5% -Tol, C0G, 30ppm/Cel TC, 0.000033uF, Surface Mount, 0603; Manufacturer: KEMET; Manufacturer Part Number: C0603C330J1GACTU; Multilayer: Yes
C711 C716 = C_0603: Ceramic Capacitor, Multilayer, Ceramic, 100V, 5% +Tol, 5% -Tol, C0G, -/+30ppm/Cel TC, 0.0022uF, Surface Mount, 0603; Manufacturer: KEMET; Manufacturer Part Number: C0603H222J1GACTU; Capacitance: 2.2nF; Multilayer: Yes
C712 C714 = C_0603: Ceramic Capacitor, Multilayer, Ceramic, 100V, 5% +Tol, 5% -Tol, C0G, 30ppm/Cel TC, 0.000022uF, Surface Mount, 0603; Manufacturer: KEMET; Manufacturer Part Number: C0603C220J1GACTU; Capacitance: 22pF; Multilayer: Yes
C713 C715 = C_0603: Ceramic Capacitor, Multilayer, Ceramic, 100V, 5% +Tol, 5% -Tol, C0G, 30ppm/Cel TC, 0.00013uF, Surface Mount, 0603; Manufacturer: Murata; Manufacturer Part Number: GRM1885C2A131JA01D; Capacitance: 130pF; Multilayer: Yes
D700 D704 D705 = CMP-1060-00492-1: DIODE ZENER 20V 500MW SOD123; Manufacturer: MCC; Manufacturer Part Number: MMSZ5250B-TP; Tolerance: 5%; Forward Voltage: 900mV; Impedance: 25R; Max Reverse Leakage Current: 100nA; Test Current: 6.2mA; Element Configuration: Single
D701 = CMP-2000-07176-1: Low Drop Power Schottky Rectifier, 2 A, 25 V, 2-Pin SMD (SMB), RoHS, Tape and Reel; Manufacturer: STMicroelectronics; Forward Current: 2A; Max Reverse Current: 90uA; Peak Non-Repetitive Surge Current: 75A; Max Repetitive Reverse Voltage (Vrrm): 25V; Element Configuration: Single; Forward Voltage: 530mV; Polarity: Standard
D702 D703 = CMP-0895-00001-2: Switching Diode, 2-Pin SOD-123, Pb-Free, Tape and Reel; Manufacturer: On Semiconductor; trr Max (ns): 4; IF Max (A): 0.2; Configuration: Single
J700-J702 = Header 2: as J605 on sheet STEVAL-KITXCBN_NFC
L700-L702 = CMP-1396-00035-1: SMD-Shielded Power Inductor WE-PD, L=10.0 µH; Manufacturer: Wuerth Elektronik; Inductance: 10.0 ÂµH
L703 L705 = CMP-06042-016297-1: FIXED IND 470NH 1.4A 70 MOHM SMD; Tolerance: 20%; Test Frequency: 1MHz; Self Resonant Frequency: 80MHz; DC Resistance (DCR): 87.5mR; Shielding: Shielded; Core Material: Ferrite
L704 = 42: Cooktop Balun / Wurth 750371385; ID: 42
M700 = P-MOS RSR020P05TL: Mosfet P-ch 30V 2A S-mini; Manufacturer: Toshiba; Rds On Max: 150mR; Input Capacitance: 159pF; Max Power Dissipation: 600mW
M701 = NMOS STT6N3LLH6: Trans MOSFET N-CH 30V 6A 6-Pin SOT-23 T/R; pin to pad: 1>5 2>5 6>5; Manufacturer: STMicroelectronics; Rise Time: 11.2ns; Rds On Max: 25mR; Input Capacitance: 283pF; Fall Time: 5.4ns; Drain to Source Resistance: 40mR; Power Dissipation: 1.6W; Turn-Off Delay Time: 9.4ns; Turn-On Delay Time: 4.8ns; Element Configuration: Single; Gate to Source Voltage (Vgs): 20V; Polarity: N-CHANNEL
M702 = NDC7002N: Transistor MOSFET Array Dual N-CH 45V 6-Pin SOT-457T Emboss T/R; Manufacturer: Rohm; Continuous Drain Current (ID): 1A; Threshold Voltage: 1.5V; Max Power Dissipation: 1.25W
NFC_Ant.700 = HEADER3: Manufacturer: Würth Electronics; Manufacturer Part Number: 691214310003; TSL: Yes; Value: MKDS 1/3-3.81
P700 = Header 2X2: Header, 2-Pin, Dual row; Value: 0
R700 = R_0603: Fixed Resistor, Thin Film, 0.1W, 10000ohm, 75V, 1% +/-Tol, 50ppm/Cel, Surface Mount, 0603; Manufacturer: Yageo; Manufacturer Part Number: RT0603FRE0710KL; Rated Power Dissipation (P): 100mW; Resistance: 10kR; Temperature Coefficient: 50ppm/°C; Rated Temperature: 70°C; Package Height: 0.45mm; Package Length: 1.6mm; Package Width: 0.8mm
R701 = R_0603: Fixed Resistor, Thin Film, 0.0625W, 2000ohm, 75V, 0.5% +/-Tol, 25ppm/Cel, Surface Mount, 0603; Manufacturer: Susumu; Manufacturer Part Number: RR0816P-202-D; Rated Power Dissipation (P): 62.5mW; Resistance: 2kR; Temperature Coefficient: 25ppm/°C; Package Height: 0.4mm; Package Length: 1.6mm; Package Width: 0.8mm
R702 = R_0603: Fixed Resistor, Metal Glaze/thick Film, 0.1W, 4220ohm, 75V, 1% +/-Tol, 100ppm/Cel, Surface Mount, 0603; Manufacturer: Vishay; Manufacturer Part Number: CRCW06034K22FKEA; Rated Power Dissipation (P): 100mW; Rated Temperature: 70°C; Resistance: 4.22kR; Temperature Coefficient: 100ppm/°C; Package Height: 0.45mm; Package Length: 1.55mm; Package Width: 0.85mm; Reference Standard: AEC-Q200
R703 = R_0805: Fixed Resistor, Metal Glaze/thick Film, 0.125W, 330000ohm, 150V, 1% +/-Tol, 100ppm/Cel, Surface Mount, 0805; Manufacturer: Panasonic; Manufacturer Part Number: ERJ6ENF3303V; Rated Power Dissipation (P): 125mW; Rated Temperature: 70°C; Temperature Coefficient: 100ppm/°C; Package Height: 0.6mm; Package Length: 2mm; Package Width: 1.25mm; Reference Standard: AEC-Q200
R704 = R_0603: Fixed Resistor, Metal Glaze/thick Film, 0.1W, 2ohm, 75V, 5% +/-Tol, 200ppm/Cel, Surface Mount, 0603; Manufacturer: Vishay Dale; Manufacturer Part Number: CRCW06032R00JNEA; Value: 2; Rated Power Dissipation (P): 100mW; Rated Temperature: 70°C; Temperature Coefficient: 200ppm/°C; Package Height: 0.45mm; Package Length: 1.55mm; Package Width: 0.85mm; Reference Standard: AEC-Q200
R705 R707 = R_0805: as R610 on sheet STEVAL-KITXCBN_NFC
R706 = R_0603: Res General Purpose Thick Film 0603 40.2K Ohm 1% 1/10W ±100ppm/°C Molded SMD Paper T/R; Manufacturer: Yageo; Manufacturer Part Number: RC0603FR-0740K2L; Rated Power Dissipation (P): 100mW; Rated Temperature: 70°C; Resistance: 40.2kR; Working Voltage: 75V; Additional Feature: LASER TRIMMABLE; Package Height: 0.45mm; Package Length: 1.6mm; Package Width: 0.8mm
R708 = R_0805
R709 R710 = R_0805: Fixed Resistor, Thin Film, 0.1W, 10ohm, 100V, 0.1% +/-Tol, 10ppm/Cel, Surface Mount, 0805; Manufacturer: TE Connectivity Holsworthy; Manufacturer Part Number: RN73C2A10RBTG; Manufacturer Series: RN73; Rated Power Dissipation (P): 100mW; Temperature Coefficient: 10ppm/°C; Additional Feature: PRECISION; Rated Temperature: 70°C
R711 = R_0603: Res Thick Film 0603 47K Ohm 1% 1/10W ±100ppm/°C Molded SMD SMD Paper T/R; Manufacturer: Yageo; Manufacturer Part Number: AC0603FR-0747KL; Power Rating: 100mW; Voltage Rating: 50V
R712 R716 = R_0603: Fixed Resistor, Thin Film, 0.1W, 100ohm, 100V, 0.1% +/-Tol, 25ppm/Cel, Surface Mount, 0603; Manufacturer: Susumu; Manufacturer Part Number: RG1608P-101-B-T5; Additional Feature: ANTI-SULFUR, PRECISION; Rated Power Dissipation (P): 166.7mW; Rated Temperature: 70°C; Temperature Coefficient: 25ppm/°C; Package Height: 0.4mm; Package Length: 1.6mm; Package Width: 0.8mm; Reference Standard: AEC-Q200
R713 R717 = R_0603: Res Thick Film 0603 1M Ohm 1% 1/10W ±100ppm/°C Molded SMD Paper T/R; Manufacturer: Yageo; Manufacturer Part Number: AC0603FR-071ML; Resistance: 1MR; Max Power Dissipation: 100mW; Voltage Rating: 50V
R714 R715 = R_0603: as R602 on sheet STEVAL-KITXCBN_NFC
T700 = NPN STD1802T4: TRANS NPN 60V 3A DPAK; Manufacturer: STMicroelectronics; Max Power Dissipation: 15W; Collector Base Voltage (VCBO): 80V; Frequency: 150MHz; Number of Elements: 1; Emitter Base Voltage (VEBO): 6V
U700 = CMP-0018-00445-1: Wideband Operational Amplifier, 2.7 to 5 V, -40 to 85 degC, 5-pin SOT23 (DBV5), Green (RoHS & no Sb/Br); Manufacturer: Texas Instruments; Vio(Max)(mV): 4; Sub Family: High Output Current Amplifier (>=50mA), High Speed Amplifier (>=50MHz); Vs(Max)(V): 5; Slew Rate(Typ)(V/us): 830; Io(Typ)(mA): 100; Acl, min stable gain(V/V): 1; Vs(Min)(V): 2.7

## Sheet STEVAL-KITXCBN_Power-Supply.SchDoc
size A4; DocumentNumber: 3; SheetNumber: 3; SheetTotal: 7; SPICEModelCacheFQSZQDRL: <root> / <DocumentId>FQSZQDRL</DocumentId> / <CacheFrame Number="0"> / <Model Name="10tq045" Kind="MDL"> / <Text>*10TQ045 MCE 3/26/98 / *Ref: IR Power Semiconductors Product Digest '94 / *MCE 45V 10A 3us pkg:TO-220 3,1 / .MODEL 10TQ045 D (IS=14.2N RS=4.2M N=1.7 BV=45 IBV=15M / + CJO=412P VJ=0.75 M=0.333 TT=4.32U EG=.69 XTI=2)</Text> / </Model> / <Model Name="skydiode" Kind="MDL"> / <Text>*Default Schottky Diode / *Schottky Diode Pinout: A,K / .MODEL SKYDIODE D(EG=0.69 XTI=2)</Text> / </Model> / </CacheFrame> / </root>
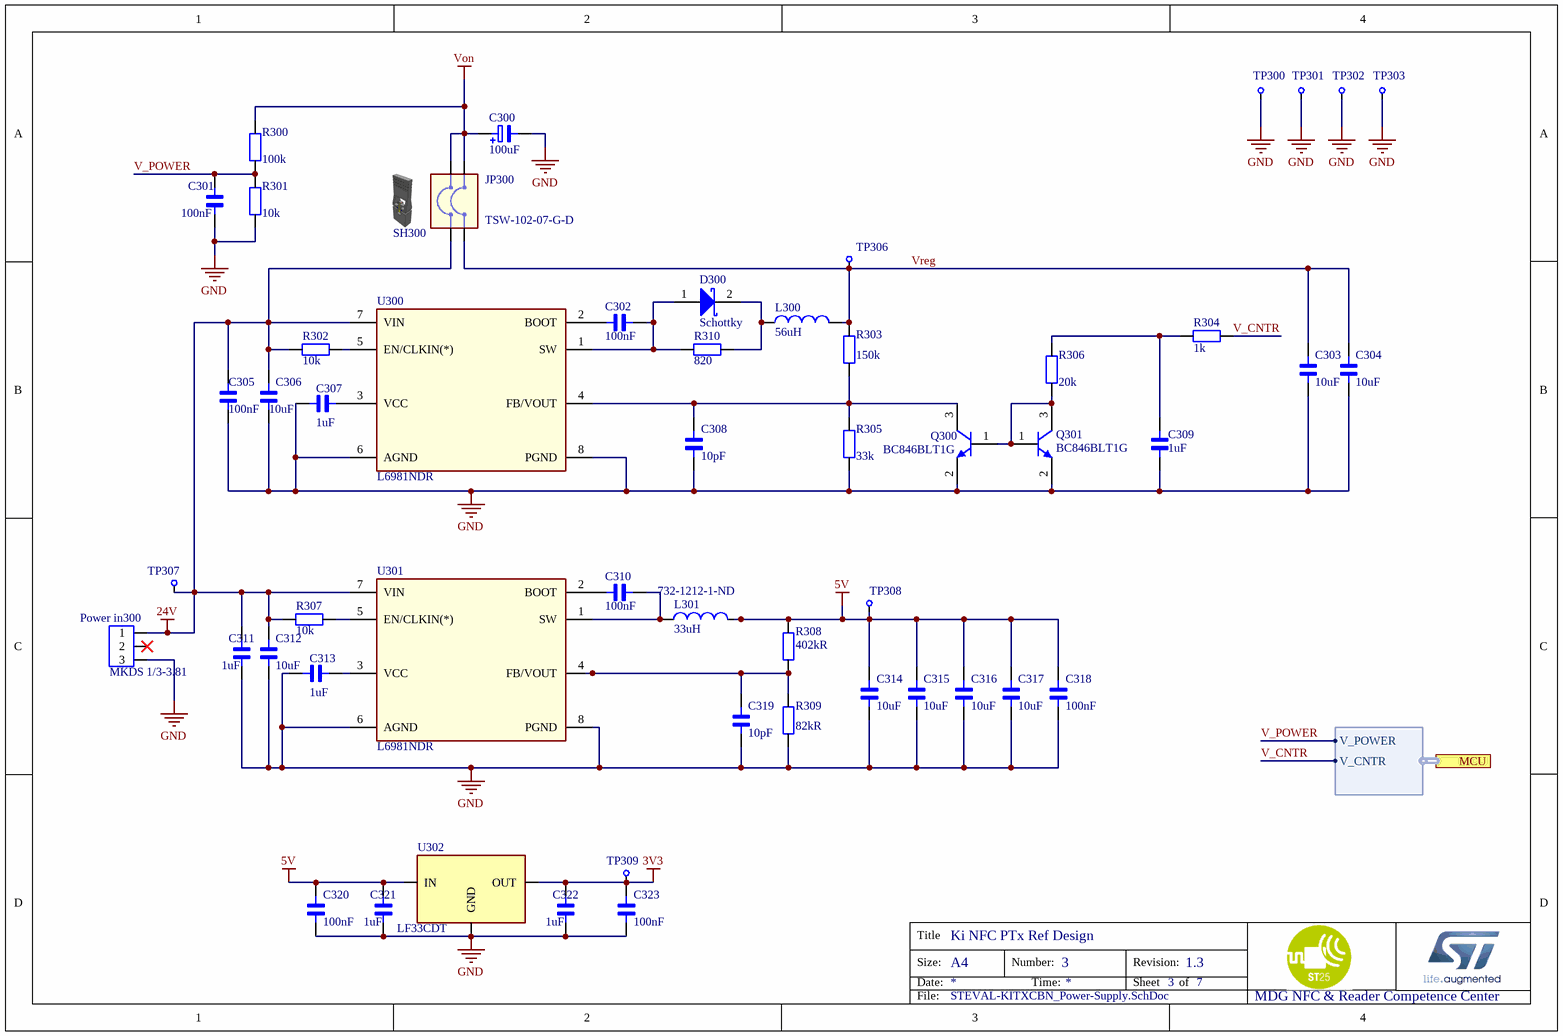
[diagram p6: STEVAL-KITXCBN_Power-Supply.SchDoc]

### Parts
C300  100uF  [ECAP 10XP5  H14]
C301  100nF  [CAP_SMD_0805]
C302  100nF  [CAP_SMD_0603]
C303  10uF  [CAP_SMD_0805]
C304  10uF  [CAP_SMD_0805]
C305  100nF  [CAP_SMD_0805]
C306  10uF  [CAP_SMD_0805]
C307  1uF  [CAP_SMD_0805]
C308  10pF  [CAP_SMD_0805]
C309  1uF  [CAP_SMD_0805]
C310  100nF  [CAP_SMD_0805]
C311  1uF  [CAP_SMD_0805]
C312  10uF  [CAP_SMD_0805]
C313  1uF  [CAP_SMD_0805]
C314  10uF  [CAP_SMD_0805]
C315  10uF  [CAP_SMD_0805]
C316  10uF  [CAP_SMD_0805]
C317  10uF  [CAP_SMD_0805]
C318  100nF  [CAP_SMD_0805]
C319  10pF  [CAP_SMD_0805]
C320  100nF  [CAP_SMD_0805]
C321  1uF  [CAP_SMD_0805]
C322  1uF  [CAP_SMD_0805]
C323  100nF  [CAP_SMD_0805]
D300  Schottky  [SMB]
JP300  TSW-102-07-G-D  [Jump2V]
L300  56uH  [WE-PD-L]
L301  33uH  Supplier Part Number 1: 732-1212-1-ND  [WE-PD-L]
Power_in300  value MKDS 1/3-3.81  [TERMINAL MKDS 1/ 3-3.81]  (hidden comment: Screw Terminal)
Q300  BC846BLT1G  [ONSC-SOT-23-3-318-08_V]
Q301  BC846BLT1G  [ONSC-SOT-23-3-318-08_V]
R300  100k  [RES_SMD_0805]
R301  10k  [RES_SMD_0805]
R302  10k  [RES_SMD_0805]
R303  150k  [RES_SMD_0805]
R304  1k  [RES_SMD_0805]
R305  33k  [RES_SMD_0805]
R306  20k  [RES_SMD_0805]
R307  10k  [RES_SMD_0805]
R308  402kR  [RES_SMD_0805]
R309  82kR  [RES_SMD_0805]
R310  820  [RES_SMD_0805]
SH300  Jumper Shunt  (value not drawn)  (mechanical)
TP300  Gnd  [TESTPOINT_BLACK]  (value not drawn)
TP301  Gnd  [TESTPOINT_BLACK]  (value not drawn)
TP302  Gnd  [TESTPOINT_BLACK]  (value not drawn)
TP303  Gnd  [TESTPOINT_BLACK]  (value not drawn)
TP306  Vreg  [TESTPOINT_RED]  (value not drawn)
TP307  24V  [TESTPOINT_RED]  (value not drawn)
TP308  5V  [TESTPOINT_RED]  (value not drawn)
TP309  3V3  [TESTPOINT_RED]  (value not drawn)
U300  L6981NDR  [SOIC-8]
U301  L6981NDR  [SOIC-8]
U302  LF33CDT  [TO-252 DPAK]

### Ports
MCU (harness MCU)

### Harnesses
MCU: V_POWER, V_CNTR

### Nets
3V3: C322.1 C323.2 TP309.1(AmpIn) U302.3(OUT)
5V: C314.2 C315.2 C316.2 C317.2 C318.2 C320.2 C321.1 L301.2 R308.2 TP308.1(AmpIn) U302.1(IN)
24V: C305.2 C306.2 C311.1 C312.2 JP300.4 Power_in300.1 R302.2 R307.2 TP307.1(AmpIn) U300.7(VIN) U301.7(VIN)
GND: C300.2(Neg) C301.1 C303.1 C304.1 C305.1 C306.1 C307.2 C308.2 C309.2 C311.2 C312.1 C313.2 C314.1 C315.1 C316.1 C317.1 C318.1 C319.2 C320.1 C321.2 C322.2 C323.1 Power_in300.3 Q300.2(E) Q301.2(E) R301.1 R305.1 R309.1 TP300.1(AmpIn) TP301.1(AmpIn) TP302.1(AmpIn) TP303.1(AmpIn) U300.6(AGND) U300.8(PGND) U301.6(AGND) U301.8(PGND) U302.2(GND)
Von: C300.1(Pos) JP300.1 JP300.3 R300.2
V_CNTR: R304.1 ; port MCU.V_CNTR
V_POWER: C301.2 R300.1 R301.2 ; port MCU.V_POWER
Vreg: C303.2 C304.2 JP300.2 L300.2 R303.2 TP306.1(AmpIn)
NetC302_1: C302.1 U300.2(BOOT)
NetC302_2: C302.2 D300.1(A) R310.2 U300.1(SW)
NetC307_1: C307.1 U300.3(VCC)
NetC308_1: C308.1 Q300.3(C) R303.1 R305.2 U300.4(FB/VOUT)
NetC309_1: C309.1 R304.2 R306.2
NetC310_1: C310.1 L301.1 U301.1(SW)
NetC310_2: C310.2 U301.2(BOOT)
NetC313_1: C313.1 U301.3(VCC)
NetC319_1: C319.1 R308.1 R309.2 U301.4(FB/VOUT)
NetD300_2: D300.2(K) L300.1 R310.1
NetQ300_1: Q300.1(B) Q301.1(B) Q301.3(C) R306.1
NetR302_1: R302.1 U300.5(EN/CLKIN(*))
NetR307_1: R307.1 U301.5(EN/CLKIN(*))

Not connected (* = marked no-connect by the designer): Power_in300 2*

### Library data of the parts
C300 = CAP P: Alum. Electrolytic Cap 100µF 63V 10mm Radial WCAP-ATUL; Lifetime 7000h +105°C; Manufacturer 1: Wurth Electronics; Manufacturer Part Number: 860040775006; Manufacturer: Würth Electronics; Polarity: Polar; Ripple Current: 640mA; Impedance: 340mR; Life (Hours): 7000Hour
C301-C307 C309-C318 C320-C323 = CAP NP: Capacitor; TSL: Yes
C308 C319 = CAP NP: Ceramic Capacitor, Multilayer, Ceramic, 50V, 5% +Tol, 5% -Tol, C0G, 30ppm/Cel TC, 0.00001uF, Surface Mount, 0805; Manufacturer: Kyocera AVX; Manufacturer Part Number: 08055A100JAT2A; Multilayer: Yes
D300 = D Schottky: Diode Schottky 40V 2A DO214AC Sm; Manufacturer: Comchip; Manufacturer Part Number: SS24-HF
JP300 = JUMPER2V: 2x2 Pin Header; TSL: Yes
L300 = CMP-0227-00732-1: SMD-Shielded Power Inductor WE-PD, L = 56.0 µH; Manufacturer: Wurth Electronics; Manufacturer Part Number: 744771156; Inductance: 56.0 ÂµH; Core Material: Ferrite; Tolerance: 20%; Case/Size Code: 4747; DC Resistance (DCR): 0.11mR; Inductor Type: GENERAL PURPOSE INDUCTOR; Number of Functions: 1; Rated Current-Max: 2.01A; Self Resonant Frequency: 7MHz; Shape/Size Description: RECTANGULAR PACKAGE; Shielding: Unshielded; Test Frequency: 1kHz
L301 = CMP-0227-00726-1: SMD-Shielded Power Inductor WE-PD, L = 33.0 µH; Manufacturer: Wurth Electronics; Manufacturer Part Number: 744771133; Inductance: 33.0 ÂµH; Core Material: Ferrite; Tolerance: 20%; Case/Size Code: 4747; DC Resistance (DCR): 57mR; Inductor Type: GENERAL PURPOSE INDUCTOR; Number of Functions: 1; Rated Current-Max: 2.68A; Self Resonant Frequency: 10MHz; Shape/Size Description: RECTANGULAR PACKAGE; Shielding: Unshielded; Test Frequency: 1kHz; Package Height: 6mm; Package Length: 12mm
Power_in300 = HEADER3: Manufacturer: Würth Electronics; Manufacturer Part Number: 691214310003; TSL: Yes
Q300 Q301 = CMP-1048-00779-1: General Purpose Transistor, NPN Silicon, 3-Pin SOT-23, Pb-Free, Tape and Reel; Manufacturer: On Semiconductor; fT Min (MHz): 100; IC Continuous (A): 0.1
R300-R302 R307 = RESISTOR: TSL: Yes; Tolerance: 1%
R303 = RESISTOR: Res Thin Film 0805 150K Ohm 0.1% 1/8W ±25ppm/°C Molded SMD SMD Punched Carrier T/R; Manufacturer: Panasonic; Manufacturer Part Number: ERA-6AEB154V; Resistance: 150kR; Power Rating: 125mW; Voltage Rating: 100V
R304 = RESISTOR: Res Thick Film 0805 1KOhm 1% 0.125W(1/8W) 100ppm/C Epoxy Pad SMD T/R; Manufacturer: Yageo; Manufacturer Part Number: RC0805FR-071KL; Resistance: 1kR; Power Rating: 125mW; Voltage Rating: 150V; Temperature Coefficient: 100ppm/°C
R305 = RESISTOR: Res Thick Film 0805 33K Ohm 5% 1/8W ±200ppm/°C Molded SMD Embossed Carrier T/R; Manufacturer: Panasonic; Manufacturer Part Number: ERJ-6GEYJ333V; Resistance: 33kR; Power Rating: 125mW; Voltage Rating: 150V
R306 = RESISTOR: Res Thick Film 0805 20K Ohm 1% 1/8W +/-100ppm/ßC Molded SMD Punched Carrier T/R; Manufacturer: Panasonic; Manufacturer Part Number: ERJ-6ENF2002V; Resistance: 20kR; Power Rating: 125mW; Voltage Rating: 150V; Temperature Coefficient: 100ppm/°C
R308 = RESISTOR: Fixed Resistor, Metal Glaze/thick Film, 0.125W, 402000ohm, 150V, 1% +/-Tol, 100ppm/Cel, Surface Mount, 0805; Manufacturer: Panasonic; Manufacturer Part Number: ERJ-6ENF4023V; Rated Power Dissipation (P): 125mW; Rated Temperature: 70°C; Temperature Coefficient: 100ppm/°C; Package Height: 0.6mm; Package Length: 2mm; Package Width: 1.25mm; Reference Standard: AEC-Q200
R309 = RESISTOR: Fixed Resistor, Thin Film, 0.125W, 82000ohm, 150V, 0.1% +/-Tol, 25ppm/Cel, Surface Mount, 0805; Manufacturer: Yageo; Manufacturer Part Number: RT0805BRD0782KL; Rated Power Dissipation (P): 125mW; Temperature Coefficient: 25ppm/°C; Rated Temperature: 70°C; Additional Feature: HIGH PRECISION; Package Height: 0.5mm; Package Length: 2mm; Package Width: 1.25mm
R310 = RESISTOR: Res Thick Film 0805 820 Ohm 1% 0.125W ±100ppm/°C Molded SMD Punched Carrier T/R; Manufacturer: Panasonic; Manufacturer Part Number: ERJ-6ENF8200V; Resistance: 820R; Power Rating: 125mW; Voltage Rating: 150V
SH300 = Jumper Shunt: Jumper Shunt 2.54mm Black; Manufacturer: Würth Electronics; Manufacturer Part Number: 609002115121; Contact Resistance: 5mR; Max Current Rating: 2.5A; Number of Contacts: 2
TP300-TP303 TP306-TP309 = TESTP: Test Point
U300 U301 = Voltage Regulator L6981: Switching Regulator; Manufacturer: STMicroelectronics
U302 = Voltage Regulator LDF33DT-TR: LFXX Series 500 mA 3.3 V Fixed VLDO Voltage Regulator with Inhibit - TO-252; Manufacturer 1: STMicroelectronics; Manufacturer Part Number 1: LF33CDT-TR; Manufacturer: STMicroelctronics; Output Voltage Accuracy: 2%; Input Bias Current: 500uA; Min Output Voltage: 3.3V

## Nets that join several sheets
3V3: STEVAL-KITXCBN_MCU-Connector (J500.3 P501.7), STEVAL-KITXCBN_Microcontroller (15 pins), STEVAL-KITXCBN_NFC (C600.2 C618.1 U600.5 U601.1), STEVAL-KITXCBN_Power-Supply (C322.1 C323.2 TP309.1 U302.3)
5V: STEVAL-KITXCBN_MCU-Connector (P501.5), STEVAL-KITXCBN_NFC (J611.2), STEVAL-KITXCBN_Power-Supply (11 pins)
24V: STEVAL-KITXCBN_MCU-Connector (P501.1), STEVAL-KITXCBN_Power-Supply (11 pins)
GND: STEVAL-KITXCBN_MCU-Connector (13 pins), STEVAL-KITXCBN_Microcontroller (29 pins), STEVAL-KITXCBN_NFC (38 pins), STEVAL-KITXCBN_Powerstage (26 pins), STEVAL-KITXCBN_Power-Supply (37 pins)
Von: STEVAL-KITXCBN_Powerstage (10 pins), STEVAL-KITXCBN_Power-Supply (C300.1 JP300.1 JP300.3 R300.2)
